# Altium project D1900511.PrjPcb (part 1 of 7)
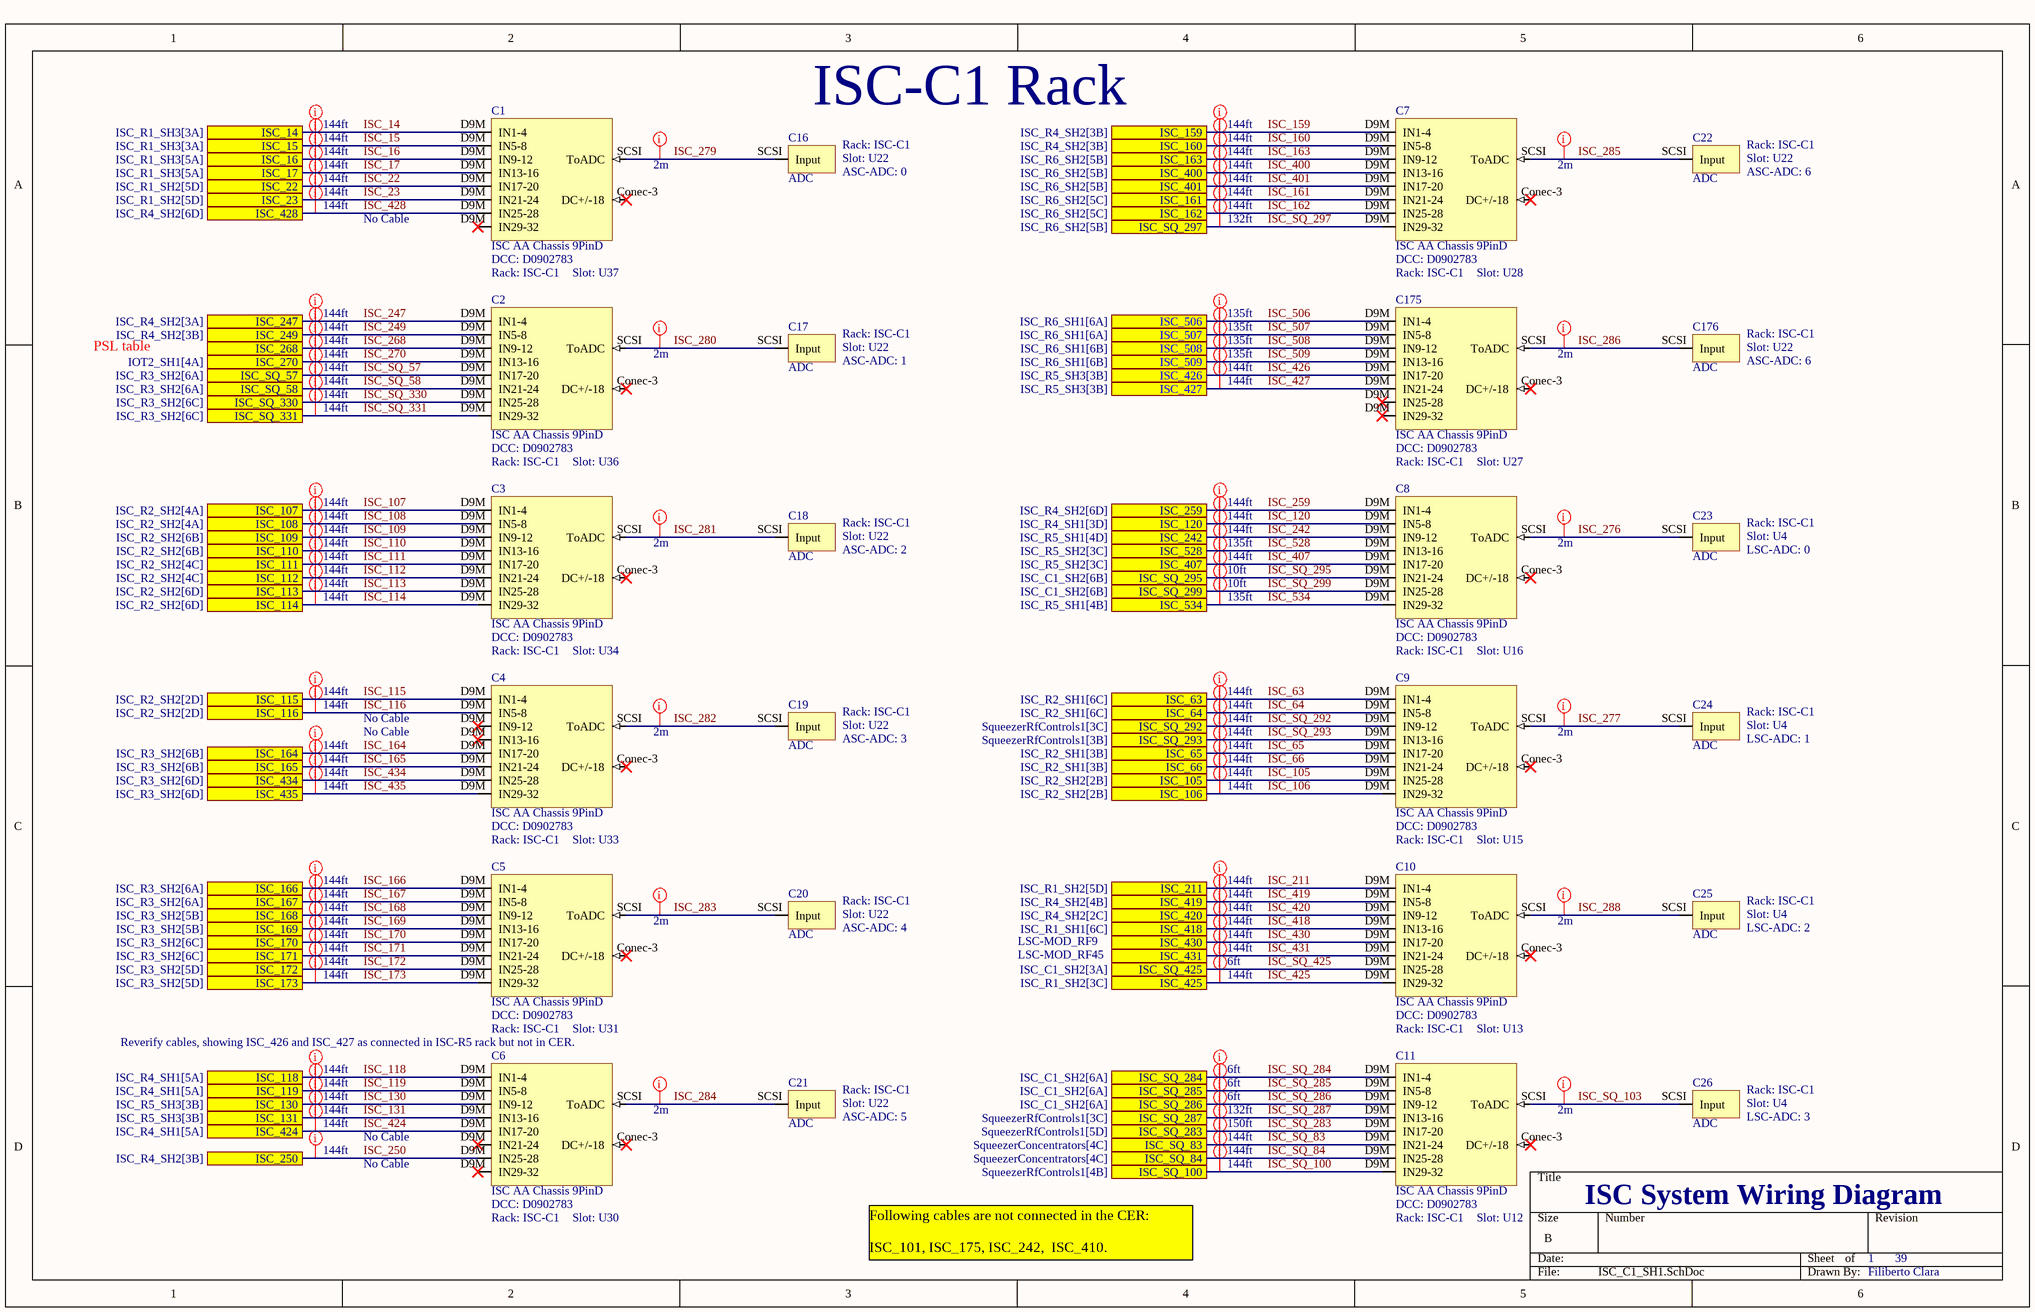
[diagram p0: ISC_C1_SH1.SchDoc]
DCCVER: V11; DCC: D1900511
39 sheets, 544 parts. Net scope: flat (ports and power ports of the same name join across sheets).
Sheets:
  ISC_C1_SH1.SchDoc
  ISC_C1_SH2.SchDoc
  ISC_C2_SH1.SchDoc
  ISC_C2_SH2.SchDoc
  ISC_C3_SH1.SchDoc
  ISC_C3_SH2.SchDoc
  ISC_C3_SH3.SchDoc
  ISC_C4_SH1.SchDoc
  ISC_C4_SH2.SchDoc
  ISC_R1_SH1.SchDoc
  ISC_R1_SH2.SchDoc
  ISC_R1_SH3.SchDoc
  ISC_R2_SH1.SchDoc
  ISC_R2_SH2.SchDoc
  ISC_R4_SH1.SchDoc
  ISC_R4_SH2.SchDoc
  ISC_R3_SH1.SchDoc
  ISC_R3_SH2.SchDoc
  ISC_R5_SH1.SchDoc
  ISC_R5_SH2.SchDoc
  ISC_R5_SH3.SchDoc
  ISC_R6_SH1.SchDoc
  ISC_R6_SH2.SchDoc
  ISCT1_SH1.SchDoc
  ISCT1_SH2.SchDoc
  IOT2_SH1.SchDoc
  IOT2_SH2.SchDoc
  HAM6_SH1.SchDoc
  HAM6_SH2.SchDoc
  SqueezerWfsWiring.SchDoc
  SqueezerInVacControls.SchDoc
  SqueezerFiber.SchDoc
  SqueezerRfDistribution.SchDoc
  SqueezerRfControls1.SchDoc
  SqueezerRfControls2.SchDoc
  SqueezerConcentrators.SchDoc
  SqueezerMiscellaneous.SchDoc
  SqueezerBeckhoff1.SchDoc
  SqueezerBeckhoff2.SchDoc

## Sheet ISC_C1_SH1.SchDoc: ISC System Wiring Diagram
size B; DrawnBy: Filiberto Clara; Engineer: Filiberto Clara; Organization: LIGO Laboratory; Address1: California Institute of Technology; Address2: Massachusetts Institute of Technology; DocumentNumber: D1900511; Revision: V11; SheetNumber: 1; SheetTotal: 39

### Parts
C1  ISC AA Chassis 9PinD  DCC: D0902783  Rack: ISC-C1  Slot: U37
C2  ISC AA Chassis 9PinD  DCC: D0902783  Rack: ISC-C1  Slot: U36
C3  ISC AA Chassis 9PinD  DCC: D0902783  Rack: ISC-C1  Slot: U34
C4  ISC AA Chassis 9PinD  DCC: D0902783  Rack: ISC-C1  Slot: U33
C5  ISC AA Chassis 9PinD  DCC: D0902783  Rack: ISC-C1  Slot: U31
C6  ISC AA Chassis 9PinD  DCC: D0902783  Rack: ISC-C1  Slot: U30
C7  ISC AA Chassis 9PinD  DCC: D0902783  Rack: ISC-C1  Slot: U28
C8  ISC AA Chassis 9PinD  DCC: D0902783  Rack: ISC-C1  Slot: U16
C9  ISC AA Chassis 9PinD  DCC: D0902783  Rack: ISC-C1  Slot: U15
C10  ISC AA Chassis 9PinD  DCC: D0902783  Rack: ISC-C1  Slot: U13
C11  ISC AA Chassis 9PinD  DCC: D0902783  Rack: ISC-C1  Slot: U12
C16  ADC  Rack: ISC-C1  Slot: U22  ASC-ADC: 0
C17  ADC  Rack: ISC-C1  Slot: U22  ASC-ADC: 1
C18  ADC  Rack: ISC-C1  Slot: U22  ASC-ADC: 2
C19  ADC  Rack: ISC-C1  Slot: U22  ASC-ADC: 3
C20  ADC  Rack: ISC-C1  Slot: U22  ASC-ADC: 4
C21  ADC  Rack: ISC-C1  Slot: U22  ASC-ADC: 5
C22  ADC  Rack: ISC-C1  Slot: U22  ASC-ADC: 6
C23  ADC  Rack: ISC-C1  Slot: U4  LSC-ADC: 0
C24  ADC  Rack: ISC-C1  Slot: U4  LSC-ADC: 1
C25  ADC  Rack: ISC-C1  Slot: U4  LSC-ADC: 2
C26  ADC  Rack: ISC-C1  Slot: U4  LSC-ADC: 3
C175  ISC AA Chassis 9PinD  DCC: D0902783  Rack: ISC-C1  Slot: U27
C176  ADC  Rack: ISC-C1  Slot: U22  ASC-ADC: 6

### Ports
ISC_14 (see ISC_R1_SH3[3A]), ISC_15 (see ISC_R1_SH3[3A]), ISC_16 (see ISC_R1_SH3[5A]), ISC_17 (see ISC_R1_SH3[5A]), ISC_22 (see ISC_R1_SH2[5D]), ISC_23 (see ISC_R1_SH2[5D]), ISC_63 (see ISC_R2_SH1[6C]), ISC_64 (see ISC_R2_SH1[6C]), ISC_65 (see ISC_R2_SH1[3B]), ISC_66 (see ISC_R2_SH1[3B]), ISC_105 (see ISC_R2_SH2[2B]), ISC_106 (see ISC_R2_SH2[2B]), ISC_107 (see ISC_R2_SH2[4A]), ISC_108 (see ISC_R2_SH2[4A]), ISC_109 (see ISC_R2_SH2[6B]), ISC_110 (see ISC_R2_SH2[6B]), ISC_111 (see ISC_R2_SH2[4C]), ISC_112 (see ISC_R2_SH2[4C]), ISC_113 (see ISC_R2_SH2[6D]), ISC_114 (see ISC_R2_SH2[6D]), ISC_115 (see ISC_R2_SH2[2D]), ISC_116 (see ISC_R2_SH2[2D]), ISC_118 (see ISC_R4_SH1[5A]), ISC_119 (see ISC_R4_SH1[5A]), ISC_120 (see ISC_R4_SH1[3D]), ISC_130 (see ISC_R5_SH3[3B]), ISC_131 (see ISC_R5_SH3[3B]), ISC_159 (see ISC_R4_SH2[3B]), ISC_160 (see ISC_R4_SH2[3B]), ISC_161 (see ISC_R6_SH2[5C]), ISC_162 (see ISC_R6_SH2[5C]), ISC_163 (see ISC_R6_SH2[5B]), ISC_164 (see ISC_R3_SH2[6B]), ISC_165 (see ISC_R3_SH2[6B]), ISC_166 (see ISC_R3_SH2[6A]), ISC_167 (see ISC_R3_SH2[6A]), ISC_168 (see ISC_R3_SH2[5B]), ISC_169 (see ISC_R3_SH2[5B]), ISC_170 (see ISC_R3_SH2[6C]), ISC_171 (see ISC_R3_SH2[6C]), ISC_172 (see ISC_R3_SH2[5D]), ISC_173 (see ISC_R3_SH2[5D]), ISC_211 (see ISC_R1_SH2[5D]), ISC_242 (see ISC_R5_SH1[4D]), ISC_247 (see ISC_R4_SH2[3A]), ISC_249 (see ISC_R4_SH2[3B]), ISC_250 (see ISC_R4_SH2[3B]), ISC_259 (see ISC_R4_SH2[6D]), ISC_268, ISC_270 (see IOT2_SH1[4A]), ISC_400 (see ISC_R6_SH2[5B]), ISC_401 (see ISC_R6_SH2[5B]), ISC_407 (see ISC_R5_SH2[3C]), ISC_418 (see ISC_R1_SH1[6C]), ISC_419 (see ISC_R4_SH2[4B]), ISC_420 (see ISC_R4_SH2[2C]), ISC_424 (see ISC_R4_SH1[5A]), ISC_425 (see ISC_R1_SH2[3C]), ISC_426 (see ISC_R5_SH3[3B]), ISC_427 (see ISC_R5_SH3[3B]), ISC_428 (see ISC_R4_SH2[6D]), ISC_430, ISC_431, ISC_434 (see ISC_R3_SH2[6D]), ISC_435 (see ISC_R3_SH2[6D]), ISC_506 (see ISC_R6_SH1[6A]), ISC_507 (see ISC_R6_SH1[6A]), ISC_508 (see ISC_R6_SH1[6B]), ISC_509 (see ISC_R6_SH1[6B]), ISC_528 (see ISC_R5_SH2[3C]), ISC_534 (see ISC_R5_SH1[4B]), ISC_SQ_57 (see ISC_R3_SH2[6A]), ISC_SQ_58 (see ISC_R3_SH2[6A]), ISC_SQ_83 (see SqueezerConcentrators[4C]), ISC_SQ_84 (see SqueezerConcentrators[4C]), ISC_SQ_100 (see SqueezerRfControls1[4B]), ISC_SQ_283 (see SqueezerRfControls1[5D]), ISC_SQ_284 (see ISC_C1_SH2[6A]), ISC_SQ_285 (see ISC_C1_SH2[6A]), ISC_SQ_286 (see ISC_C1_SH2[6A]), ISC_SQ_287 (see SqueezerRfControls1[3C]), ISC_SQ_292 (see SqueezerRfControls1[3C]), ISC_SQ_293 (see SqueezerRfControls1[3B]), ISC_SQ_295 (see ISC_C1_SH2[6B]), ISC_SQ_297 (see ISC_R6_SH2[5B]), ISC_SQ_299 (see ISC_C1_SH2[6B]), ISC_SQ_330 (see ISC_R3_SH2[6C]), ISC_SQ_331 (see ISC_R3_SH2[6C]), ISC_SQ_425 (see ISC_C1_SH2[3A])

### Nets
ISC_14: C1.D9M(IN1-4) ; port ISC_14
ISC_15: C1.D9M(IN5-8) ; port ISC_15
ISC_16: C1.D9M(IN9-12) ; port ISC_16
ISC_17: C1.D9M(IN13-16) ; port ISC_17
ISC_22: C1.D9M(IN17-20) ; port ISC_22
ISC_23: C1.D9M(IN21-24) ; port ISC_23
ISC_63: C9.D9M(IN1-4) ; port ISC_63
ISC_64: C9.D9M(IN5-8) ; port ISC_64
ISC_65: C9.D9M(IN17-20) ; port ISC_65
ISC_66: C9.D9M(IN21-24) ; port ISC_66
ISC_105: C9.D9M(IN25-28) ; port ISC_105
ISC_106: C9.D9M(IN29-32) ; port ISC_106
ISC_107: C3.D9M(IN1-4) ; port ISC_107
ISC_108: C3.D9M(IN5-8) ; port ISC_108
ISC_109: C3.D9M(IN9-12) ; port ISC_109
ISC_110: C3.D9M(IN13-16) ; port ISC_110
ISC_111: C3.D9M(IN17-20) ; port ISC_111
ISC_112: C3.D9M(IN21-24) ; port ISC_112
ISC_113: C3.D9M(IN25-28) ; port ISC_113
ISC_114: C3.D9M(IN29-32) ; port ISC_114
ISC_115: C4.D9M(IN1-4) ; port ISC_115
ISC_116: C4.D9M(IN5-8) ; port ISC_116
ISC_118: C6.D9M(IN1-4) ; port ISC_118
ISC_119: C6.D9M(IN5-8) ; port ISC_119
ISC_120: C8.D9M(IN5-8) ; port ISC_120
ISC_130: C6.D9M(IN9-12) ; port ISC_130
ISC_131: C6.D9M(IN13-16) ; port ISC_131
ISC_159: C7.D9M(IN1-4) ; port ISC_159
ISC_160: C7.D9M(IN5-8) ; port ISC_160
ISC_161: C7.D9M(IN21-24) ; port ISC_161
ISC_162: C7.D9M(IN25-28) ; port ISC_162
ISC_163: C7.D9M(IN9-12) ; port ISC_163
ISC_164: C4.D9M(IN17-20) ; port ISC_164
ISC_165: C4.D9M(IN21-24) ; port ISC_165
ISC_166: C5.D9M(IN1-4) ; port ISC_166
ISC_167: C5.D9M(IN5-8) ; port ISC_167
ISC_168: C5.D9M(IN9-12) ; port ISC_168
ISC_169: C5.D9M(IN13-16) ; port ISC_169
ISC_170: C5.D9M(IN17-20) ; port ISC_170
ISC_171: C5.D9M(IN21-24) ; port ISC_171
ISC_172: C5.D9M(IN25-28) ; port ISC_172
ISC_173: C5.D9M(IN29-32) ; port ISC_173
ISC_211: C10.D9M(IN1-4) ; port ISC_211
ISC_242: C8.D9M(IN9-12) ; port ISC_242
ISC_247: C2.D9M(IN1-4) ; port ISC_247
ISC_249: C2.D9M(IN5-8) ; port ISC_249
ISC_250: C6.D9M(IN25-28) ; port ISC_250
ISC_259: C8.D9M(IN1-4) ; port ISC_259
ISC_268: C2.D9M(IN9-12) ; port ISC_268
ISC_270: C2.D9M(IN13-16) ; port ISC_270
ISC_276: C8.SCSI(ToADC) C23.SCSI(Input)
ISC_277: C9.SCSI(ToADC) C24.SCSI(Input)
ISC_279: C1.SCSI(ToADC) C16.SCSI(Input)
ISC_280: C2.SCSI(ToADC) C17.SCSI(Input)
ISC_281: C3.SCSI(ToADC) C18.SCSI(Input)
ISC_282: C4.SCSI(ToADC) C19.SCSI(Input)
ISC_283: C5.SCSI(ToADC) C20.SCSI(Input)
ISC_284: C6.SCSI(ToADC) C21.SCSI(Input)
ISC_285: C7.SCSI(ToADC) C22.SCSI(Input)
ISC_286: C175.SCSI(ToADC) C176.SCSI(Input)
ISC_288: C10.SCSI(ToADC) C25.SCSI(Input)
ISC_400: C7.D9M(IN13-16) ; port ISC_400
ISC_401: C7.D9M(IN17-20) ; port ISC_401
ISC_407: C8.D9M(IN17-20) ; port ISC_407
ISC_418: C10.D9M(IN13-16) ; port ISC_418
ISC_419: C10.D9M(IN5-8) ; port ISC_419
ISC_420: C10.D9M(IN9-12) ; port ISC_420
ISC_424: C6.D9M(IN17-20) ; port ISC_424
ISC_425: C10.D9M(IN29-32) ; port ISC_425
ISC_426: C175.D9M(IN17-20) ; port ISC_426
ISC_427: C175.D9M(IN21-24) ; port ISC_427
ISC_428: C1.D9M(IN25-28) ; port ISC_428
ISC_430: C10.D9M(IN17-20) ; port ISC_430
ISC_431: C10.D9M(IN21-24) ; port ISC_431
ISC_434: C4.D9M(IN25-28) ; port ISC_434
ISC_435: C4.D9M(IN29-32) ; port ISC_435
ISC_506: C175.D9M(IN1-4) ; port ISC_506
ISC_507: C175.D9M(IN5-8) ; port ISC_507
ISC_508: C175.D9M(IN9-12) ; port ISC_508
ISC_509: C175.D9M(IN13-16) ; port ISC_509
ISC_528: C8.D9M(IN13-16) ; port ISC_528
ISC_534: C8.D9M(IN29-32) ; port ISC_534
ISC_SQ_57: C2.D9M(IN17-20) ; port ISC_SQ_57
ISC_SQ_58: C2.D9M(IN21-24) ; port ISC_SQ_58
ISC_SQ_83: C11.D9M(IN21-24) ; port ISC_SQ_83
ISC_SQ_84: C11.D9M(IN25-28) ; port ISC_SQ_84
ISC_SQ_100: C11.D9M(IN29-32) ; port ISC_SQ_100
ISC_SQ_103: C11.SCSI(ToADC) C26.SCSI(Input)
ISC_SQ_283: C11.D9M(IN17-20) ; port ISC_SQ_283
ISC_SQ_284: C11.D9M(IN1-4) ; port ISC_SQ_284
ISC_SQ_285: C11.D9M(IN5-8) ; port ISC_SQ_285
ISC_SQ_286: C11.D9M(IN9-12) ; port ISC_SQ_286
ISC_SQ_287: C11.D9M(IN13-16) ; port ISC_SQ_287
ISC_SQ_292: C9.D9M(IN9-12) ; port ISC_SQ_292
ISC_SQ_293: C9.D9M(IN13-16) ; port ISC_SQ_293
ISC_SQ_295: C8.D9M(IN21-24) ; port ISC_SQ_295
ISC_SQ_297: C7.D9M(IN29-32) ; port ISC_SQ_297
ISC_SQ_299: C8.D9M(IN25-28) ; port ISC_SQ_299
ISC_SQ_330: C2.D9M(IN25-28) ; port ISC_SQ_330
ISC_SQ_331: C2.D9M(IN29-32) ; port ISC_SQ_331
ISC_SQ_425: C10.D9M(IN25-28) ; port ISC_SQ_425

Not connected (* = marked no-connect by the designer): C1 Conec-3(DC+/-18)*; C2 Conec-3(DC+/-18)*; C3 Conec-3(DC+/-18)*; C4 Conec-3(DC+/-18)*; C5 Conec-3(DC+/-18)*; C6 Conec-3(DC+/-18)*; C7 Conec-3(DC+/-18)*; C8 Conec-3(DC+/-18)*; C9 Conec-3(DC+/-18)*; C10 Conec-3(DC+/-18)*; C11 Conec-3(DC+/-18)*; C175 Conec-3(DC+/-18)*

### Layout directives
Length: 2m: ISC_276, ISC_277, ISC_279, ISC_280, ISC_281, ISC_282, ISC_283, ISC_284, ISC_285, ISC_286, ISC_288, ISC_SQ_103
Length: 144ft: ISC_14, ISC_15, ISC_16, ISC_17, ISC_22, ISC_23, ISC_63, ISC_64, ISC_65, ISC_66, ISC_105, ISC_106, ISC_107, ISC_108, ISC_109, ISC_110, ISC_111, ISC_112, ISC_113, ISC_114, ISC_115, ISC_116, ISC_118, ISC_119, ISC_120, ISC_130, ISC_131, ISC_159, ISC_160, ISC_161, ISC_162, ISC_163, ISC_164, ISC_165, ISC_166, ISC_167, ISC_168, ISC_169, ISC_170, ISC_171, ISC_172, ISC_173, ISC_211, ISC_242, ISC_247, ISC_249, ISC_250, ISC_259, ISC_268, ISC_270, ISC_400, ISC_401, ISC_407, ISC_418, ISC_419, ISC_420, ISC_424, ISC_425, ISC_426, ISC_427, ISC_428, ISC_430, ISC_431, ISC_434, ISC_435, ISC_SQ_57, ISC_SQ_58, ISC_SQ_83, ISC_SQ_84, ISC_SQ_100, ISC_SQ_292, ISC_SQ_293, ISC_SQ_330, ISC_SQ_331
Length: 10ft: ISC_SQ_295, ISC_SQ_299
Length: 132ft: ISC_SQ_287, ISC_SQ_297
Length: 6ft: ISC_SQ_284, ISC_SQ_285, ISC_SQ_286, ISC_SQ_425
Length: 150ft: ISC_SQ_283
Length: 135ft: ISC_506, ISC_507, ISC_508, ISC_509, ISC_528, ISC_534

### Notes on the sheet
- (near C16) ISC-C1 Rack
- No Cable
- PSL table
- LSC-MOD_RF9
- LSC-MOD_RF45
- (near C6) Reverify cables, showing ISC_426 and ISC_427 as connected in ISC-R5 rack but not in CER.
- Following cables are not connected in the CER:
  ISC_101, ISC_175, ISC_242,  ISC_410.

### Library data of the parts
C1-C11 C175 = AA_9pinAll: Serial: Sxxxxxxx
C16-C26 C176 = ADC-16: 16 Bit ADC; Serial: Sxxxxxxx; System: ISC; DCC: tbd

## Sheet ISC_C1_SH2.SchDoc: ISC System Wiring Diagram
size B; DrawnBy: Filiberto Clara; Engineer: Filiberto Clara; Organization: LIGO Laboratory; Address1: California Institute of Technology; Address2: Massachusetts Institute of Technology; DocumentNumber: D1900511; Revision: V11; SheetNumber: 2; SheetTotal: 39
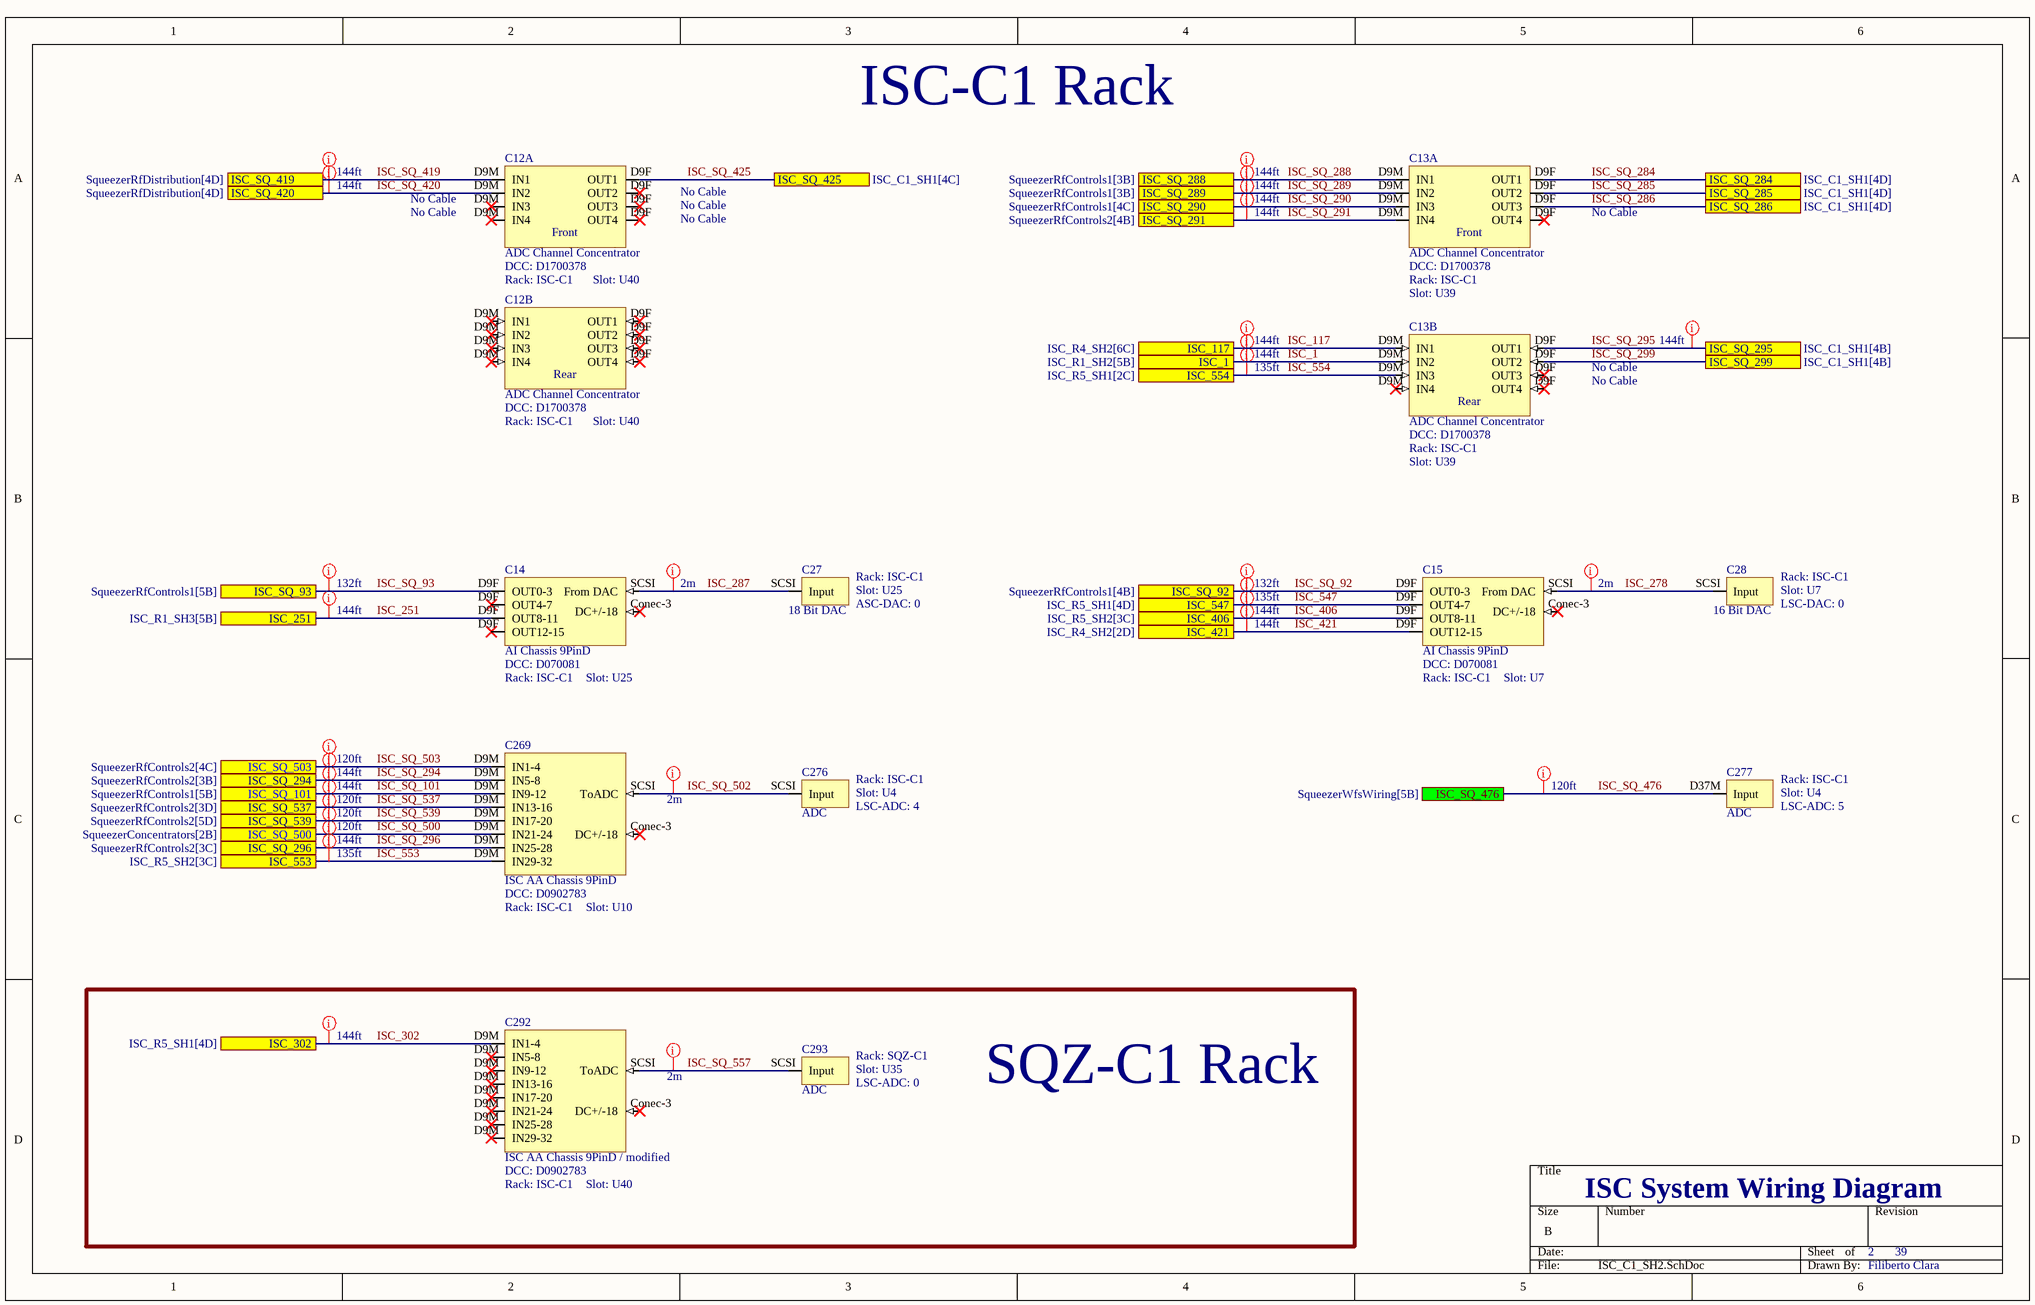
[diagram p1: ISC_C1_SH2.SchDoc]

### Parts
C12  ADC Channel Concentrator  DCC: D1700378  Rack: ISC-C1  Slot: U40  (parts A,B of 2)
C13  ADC Channel Concentrator  DCC: D1700378  Rack: ISC-C1  Slot: U39  (parts A,B of 2)
C14  AI Chassis 9PinD  DCC: D070081  Rack: ISC-C1  Slot: U25
C15  AI Chassis 9PinD  DCC: D070081  Rack: ISC-C1  Slot: U7
C27  18 Bit DAC  Rack: ISC-C1  Slot: U25  ASC-DAC: 0
C28  16 Bit DAC  Rack: ISC-C1  Slot: U7  LSC-DAC: 0
C269  ISC AA Chassis 9PinD  DCC: D0902783  Rack: ISC-C1  Slot: U10
C276  ADC  Rack: ISC-C1  Slot: U4  LSC-ADC: 4
C277  ADC  Rack: ISC-C1  Slot: U4  LSC-ADC: 5
C292  ISC AA Chassis 9PinD / modified  DCC: D0902783  Rack: ISC-C1  Slot: U40
C293  ADC  Rack: SQZ-C1  Slot: U35  LSC-ADC: 0

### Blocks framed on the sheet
SQZ-C1 Rack: C292 C293

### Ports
ISC_1 (see ISC_R1_SH2[5B]), ISC_117 (see ISC_R4_SH2[6C]), ISC_251 (see ISC_R1_SH3[5B]), ISC_302 (see ISC_R5_SH1[4D]), ISC_406 (see ISC_R5_SH2[3C]), ISC_421 (see ISC_R4_SH2[2D]), ISC_547 (see ISC_R5_SH1[4D]), ISC_553 (see ISC_R5_SH2[3C]), ISC_554 (see ISC_R5_SH1[2C]), ISC_SQ_92 (see SqueezerRfControls1[4B]), ISC_SQ_93 (see SqueezerRfControls1[5B]), ISC_SQ_101 (see SqueezerRfControls1[5B]), ISC_SQ_284 (see ISC_C1_SH1[4D]), ISC_SQ_285 (see ISC_C1_SH1[4D]), ISC_SQ_286 (see ISC_C1_SH1[4D]), ISC_SQ_288 (see SqueezerRfControls1[3B]), ISC_SQ_289 (see SqueezerRfControls1[3B]), ISC_SQ_290 (see SqueezerRfControls1[4C]), ISC_SQ_291 (see SqueezerRfControls2[4B]), ISC_SQ_294 (see SqueezerRfControls2[3B]), ISC_SQ_295 (see ISC_C1_SH1[4B]), ISC_SQ_296 (see SqueezerRfControls2[3C]), ISC_SQ_299 (see ISC_C1_SH1[4B]), ISC_SQ_419 (see SqueezerRfDistribution[4D]), ISC_SQ_420 (see SqueezerRfDistribution[4D]), ISC_SQ_425 (see ISC_C1_SH1[4C]), ISC_SQ_476 (see SqueezerWfsWiring[5B]), ISC_SQ_500 (see SqueezerConcentrators[2B]), ISC_SQ_503 (see SqueezerRfControls2[4C]), ISC_SQ_537 (see SqueezerRfControls2[3D]), ISC_SQ_539 (see SqueezerRfControls2[5D])

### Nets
ISC_1: C13.D9M(IN2) ; port ISC_1
ISC_117: C13.D9M(IN1) ; port ISC_117
ISC_251: C14.D9F(OUT8-11) ; port ISC_251
ISC_278: C15.SCSI(From_DAC) C28.SCSI(Input)
ISC_287: C14.SCSI(From_DAC) C27.SCSI(Input)
ISC_302: C292.D9M(IN1-4) ; port ISC_302
ISC_406: C15.D9F(OUT8-11) ; port ISC_406
ISC_421: C15.D9F(OUT12-15) ; port ISC_421
ISC_547: C15.D9F(OUT4-7) ; port ISC_547
ISC_553: C269.D9M(IN29-32) ; port ISC_553
ISC_554: C13.D9M(IN3) ; port ISC_554
ISC_SQ_92: C15.D9F(OUT0-3) ; port ISC_SQ_92
ISC_SQ_93: C14.D9F(OUT0-3) ; port ISC_SQ_93
ISC_SQ_101: C269.D9M(IN9-12) ; port ISC_SQ_101
ISC_SQ_284: C13.D9F(OUT1) ; port ISC_SQ_284
ISC_SQ_285: C13.D9F(OUT2) ; port ISC_SQ_285
ISC_SQ_286: C13.D9F(OUT3) ; port ISC_SQ_286
ISC_SQ_288: C13.D9M(IN1) ; port ISC_SQ_288
ISC_SQ_289: C13.D9M(IN2) ; port ISC_SQ_289
ISC_SQ_290: C13.D9M(IN3) ; port ISC_SQ_290
ISC_SQ_291: C13.D9M(IN4) ; port ISC_SQ_291
ISC_SQ_294: C269.D9M(IN5-8) ; port ISC_SQ_294
ISC_SQ_295: C13.D9F(OUT1) ; port ISC_SQ_295
ISC_SQ_296: C269.D9M(IN25-28) ; port ISC_SQ_296
ISC_SQ_299: C13.D9F(OUT2) ; port ISC_SQ_299
ISC_SQ_419: C12.D9M(IN1) ; port ISC_SQ_419
ISC_SQ_420: C12.D9M(IN2) ; port ISC_SQ_420
ISC_SQ_425: C12.D9F(OUT1) ; port ISC_SQ_425
ISC_SQ_476: C277.D37M(Input) ; port ISC_SQ_476
ISC_SQ_500: C269.D9M(IN21-24) ; port ISC_SQ_500
ISC_SQ_502: C269.SCSI(ToADC) C276.SCSI(Input)
ISC_SQ_503: C269.D9M(IN1-4) ; port ISC_SQ_503
ISC_SQ_537: C269.D9M(IN13-16) ; port ISC_SQ_537
ISC_SQ_539: C269.D9M(IN17-20) ; port ISC_SQ_539
ISC_SQ_557: C292.SCSI(ToADC) C293.SCSI(Input)

Not connected (* = marked no-connect by the designer): C14 Conec-3(DC+/-18)*; C15 Conec-3(DC+/-18)*; C269 Conec-3(DC+/-18)*; C292 Conec-3(DC+/-18)*

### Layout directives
Length: 144ft: ISC_1, ISC_117, ISC_251, ISC_302, ISC_406, ISC_421, ISC_SQ_101, ISC_SQ_288, ISC_SQ_289, ISC_SQ_290, ISC_SQ_291, ISC_SQ_294, ISC_SQ_295, ISC_SQ_296, ISC_SQ_419, ISC_SQ_420
Length: 2m: ISC_278, ISC_287, ISC_SQ_502, ISC_SQ_557
Length: 132ft: ISC_SQ_92, ISC_SQ_93
Length: 120ft: ISC_SQ_476, ISC_SQ_500, ISC_SQ_503, ISC_SQ_537, ISC_SQ_539
Length: 135ft: ISC_547, ISC_553, ISC_554

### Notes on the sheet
- ISC-C1 Rack
- (near C12) No Cable
- No Cable

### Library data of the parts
C12 C13 = ADC Channel Concentrator: Serial: Sxxxxxxx; System: ISC
C14 C15 = AI_9pinAll: Serial: Sxxxxxxx; System: ISC
C27 = DAC_18: Serial: Sxxxxxxx; System: ISC; DCC: tbd
C28 = DAC_18: 18 Bit DAC; Serial: Sxxxxxxx; System: ISC; DCC: tbd
C269 = AA_9pinAll: Serial: Sxxxxxxx
C276 C277 C293 = ADC-16: as C16 on sheet ISC_C1_SH1
C292 = AA_9pinAll: ISC AA Chassis 9PinD; Serial: Sxxxxxxx

## Sheet ISC_C2_SH1.SchDoc: ISC System Wiring Diagram
size B; DrawnBy: Filiberto Clara; Engineer: Filiberto Clara; Organization: LIGO Laboratory; Address1: California Institute of Technology; Address2: Massachusetts Institute of Technology; DocumentNumber: D1900511; Revision: V11; SheetNumber: 3; SheetTotal: 39
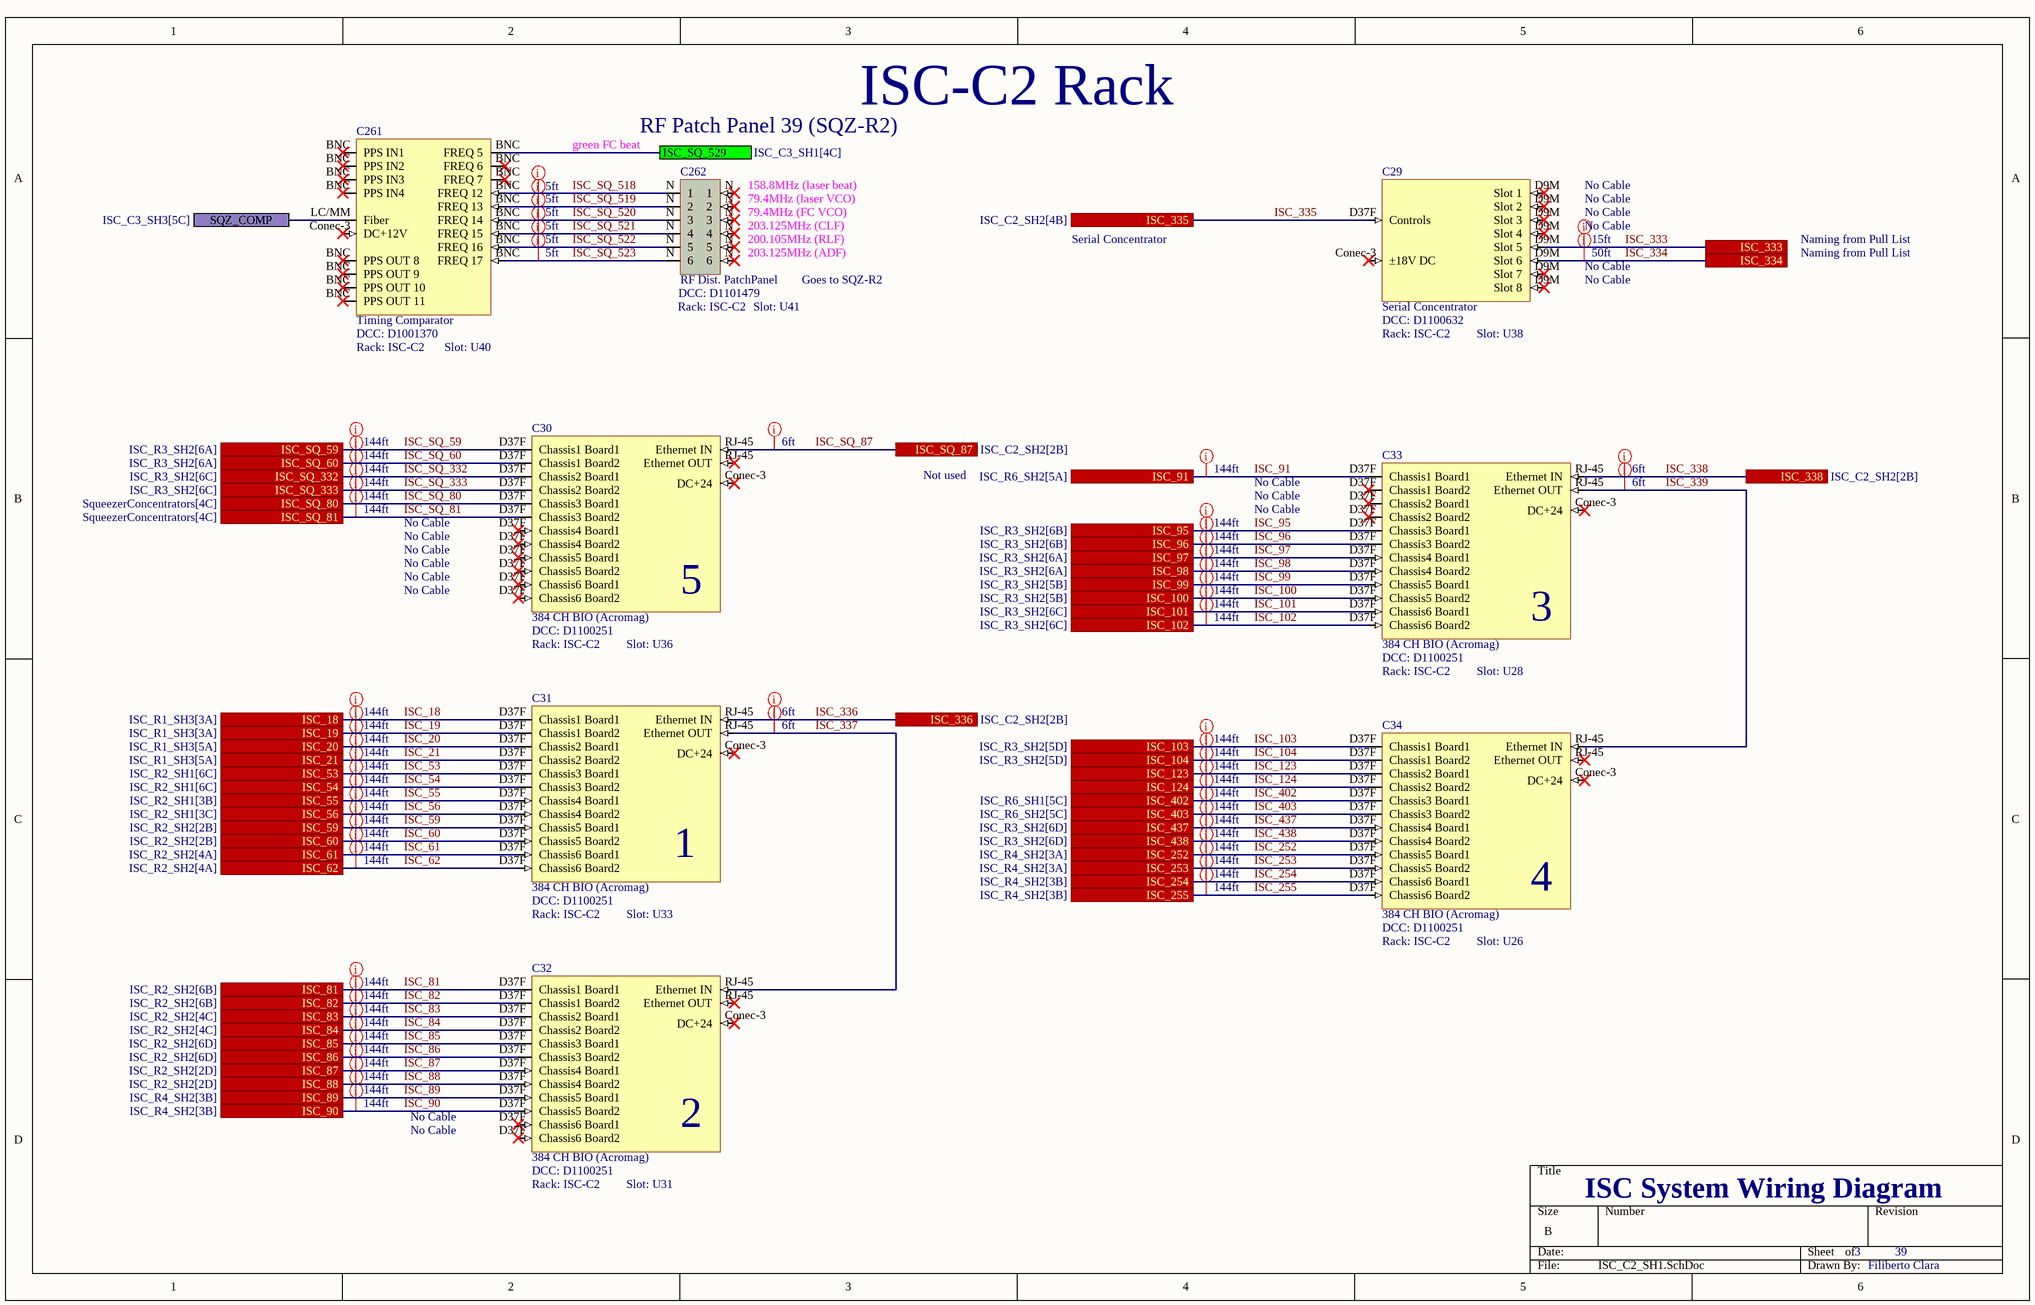
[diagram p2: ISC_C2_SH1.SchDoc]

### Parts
C29  Serial Concentrator  DCC: D1100632  Rack: ISC-C2  Slot: U38
C30  384 CH BIO (Acromag)  DCC: D1100251  Rack: ISC-C2  Slot: U36
C31  384 CH BIO (Acromag)  DCC: D1100251  Rack: ISC-C2  Slot: U33
C32  384 CH BIO (Acromag)  DCC: D1100251  Rack: ISC-C2  Slot: U31
C33  384 CH BIO (Acromag)  DCC: D1100251  Rack: ISC-C2  Slot: U28
C34  384 CH BIO (Acromag)  DCC: D1100251  Rack: ISC-C2  Slot: U26
C261  Timing Comparator  DCC: D1001370  Rack: ISC-C2  Slot: U40
C262  RF Dist. PatchPanel  DCC: D1101479  Rack: ISC-C2  Slot: U41

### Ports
ISC_18 (see ISC_R1_SH3[3A]), ISC_19 (see ISC_R1_SH3[3A]), ISC_20 (see ISC_R1_SH3[5A]), ISC_21 (see ISC_R1_SH3[5A]), ISC_53 (see ISC_R2_SH1[6C]), ISC_54 (see ISC_R2_SH1[6C]), ISC_55 (see ISC_R2_SH1[3B]), ISC_56 (see ISC_R2_SH1[3C]), ISC_59 (see ISC_R2_SH2[2B]), ISC_60 (see ISC_R2_SH2[2B]), ISC_61 (see ISC_R2_SH2[4A]), ISC_62 (see ISC_R2_SH2[4A]), ISC_81 (see ISC_R2_SH2[6B]), ISC_82 (see ISC_R2_SH2[6B]), ISC_83 (see ISC_R2_SH2[4C]), ISC_84 (see ISC_R2_SH2[4C]), ISC_85 (see ISC_R2_SH2[6D]), ISC_86 (see ISC_R2_SH2[6D]), ISC_87 (see ISC_R2_SH2[2D]), ISC_88 (see ISC_R2_SH2[2D]), ISC_89 (see ISC_R4_SH2[3B]), ISC_90 (see ISC_R4_SH2[3B]), ISC_91 (see ISC_R6_SH2[5A]), ISC_95 (see ISC_R3_SH2[6B]), ISC_96 (see ISC_R3_SH2[6B]), ISC_97 (see ISC_R3_SH2[6A]), ISC_98 (see ISC_R3_SH2[6A]), ISC_99 (see ISC_R3_SH2[5B]), ISC_100 (see ISC_R3_SH2[5B]), ISC_101 (see ISC_R3_SH2[6C]), ISC_102 (see ISC_R3_SH2[6C]), ISC_103 (see ISC_R3_SH2[5D]), ISC_104 (see ISC_R3_SH2[5D]), ISC_123, ISC_124, ISC_252 (see ISC_R4_SH2[3A]), ISC_253 (see ISC_R4_SH2[3A]), ISC_254 (see ISC_R4_SH2[3B]), ISC_255 (see ISC_R4_SH2[3B]), ISC_333, ISC_334, ISC_335 (see ISC_C2_SH2[4B]), ISC_336 (see ISC_C2_SH2[2B]), ISC_338 (see ISC_C2_SH2[2B]), ISC_402 (see ISC_R6_SH1[5C]), ISC_403 (see ISC_R6_SH2[5C]), ISC_437 (see ISC_R3_SH2[6D]), ISC_438 (see ISC_R3_SH2[6D]), ISC_SQ_59 (see ISC_R3_SH2[6A]), ISC_SQ_60 (see ISC_R3_SH2[6A]), ISC_SQ_80 (see SqueezerConcentrators[4C]), ISC_SQ_81 (see SqueezerConcentrators[4C]), ISC_SQ_87 (see ISC_C2_SH2[2B]), ISC_SQ_332 (see ISC_R3_SH2[6C]), ISC_SQ_333 (see ISC_R3_SH2[6C]), ISC_SQ_529 (see ISC_C3_SH1[4C]), SQZ_COMP (see ISC_C3_SH3[5C])

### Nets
ISC_18: C31.D37F(Chassis1_Board1) ; port ISC_18
ISC_19: C31.D37F(Chassis1_Board2) ; port ISC_19
ISC_20: C31.D37F(Chassis2_Board1) ; port ISC_20
ISC_21: C31.D37F(Chassis2_Board2) ; port ISC_21
ISC_53: C31.D37F(Chassis3_Board1) ; port ISC_53
ISC_54: C31.D37F(Chassis3_Board2) ; port ISC_54
ISC_55: C31.D37F(Chassis4_Board1) ; port ISC_55
ISC_56: C31.D37F(Chassis4_Board2) ; port ISC_56
ISC_59: C31.D37F(Chassis5_Board1) ; port ISC_59
ISC_60: C31.D37F(Chassis5_Board2) ; port ISC_60
ISC_61: C31.D37F(Chassis6_Board1) ; port ISC_61
ISC_62: C31.D37F(Chassis6_Board2) ; port ISC_62
ISC_81: C32.D37F(Chassis1_Board1) ; port ISC_81
ISC_82: C32.D37F(Chassis1_Board2) ; port ISC_82
ISC_83: C32.D37F(Chassis2_Board1) ; port ISC_83
ISC_84: C32.D37F(Chassis2_Board2) ; port ISC_84
ISC_85: C32.D37F(Chassis3_Board1) ; port ISC_85
ISC_86: C32.D37F(Chassis3_Board2) ; port ISC_86
ISC_87: C32.D37F(Chassis4_Board1) ; port ISC_87
ISC_88: C32.D37F(Chassis4_Board2) ; port ISC_88
ISC_89: C32.D37F(Chassis5_Board1) ; port ISC_89
ISC_90: C32.D37F(Chassis5_Board2) ; port ISC_90
ISC_91: C33.D37F(Chassis1_Board1) ; port ISC_91
ISC_95: C33.D37F(Chassis3_Board1) ; port ISC_95
ISC_96: C33.D37F(Chassis3_Board2) ; port ISC_96
ISC_97: C33.D37F(Chassis4_Board1) ; port ISC_97
ISC_98: C33.D37F(Chassis4_Board2) ; port ISC_98
ISC_99: C33.D37F(Chassis5_Board1) ; port ISC_99
ISC_100: C33.D37F(Chassis5_Board2) ; port ISC_100
ISC_101: C33.D37F(Chassis6_Board1) ; port ISC_101
ISC_102: C33.D37F(Chassis6_Board2) ; port ISC_102
ISC_103: C34.D37F(Chassis1_Board1) ; port ISC_103
ISC_104: C34.D37F(Chassis1_Board2) ; port ISC_104
ISC_123: C34.D37F(Chassis2_Board1) ; port ISC_123
ISC_124: C34.D37F(Chassis2_Board2) ; port ISC_124
ISC_252: C34.D37F(Chassis5_Board1) ; port ISC_252
ISC_253: C34.D37F(Chassis5_Board2) ; port ISC_253
ISC_254: C34.D37F(Chassis6_Board1) ; port ISC_254
ISC_255: C34.D37F(Chassis6_Board2) ; port ISC_255
ISC_333: C29.D9M(Slot_1) ; port ISC_333
ISC_334: C29.D9M(Slot_6) ; port ISC_334
ISC_335: C29.D37F(Controls) ; port ISC_335
ISC_336: C31.RJ-45(Ethernet_IN) ; port ISC_336
ISC_337: C31.RJ-45(Ethernet_OUT) C32.RJ-45(Ethernet_IN)
ISC_338: C33.RJ-45(Ethernet_IN) ; port ISC_338
ISC_339: C33.RJ-45(Ethernet_OUT) C34.RJ-45(Ethernet_IN)
ISC_402: C34.D37F(Chassis3_Board1) ; port ISC_402
ISC_403: C34.D37F(Chassis3_Board2) ; port ISC_403
ISC_437: C34.D37F(Chassis4_Board1) ; port ISC_437
ISC_438: C34.D37F(Chassis4_Board2) ; port ISC_438
ISC_SQ_59: C30.D37F(Chassis1_Board1) ; port ISC_SQ_59
ISC_SQ_60: C30.D37F(Chassis1_Board2) ; port ISC_SQ_60
ISC_SQ_80: C30.D37F(Chassis3_Board1) ; port ISC_SQ_80
ISC_SQ_81: C30.D37F(Chassis3_Board2) ; port ISC_SQ_81
ISC_SQ_87: C30.RJ-45(Ethernet_IN) ; port ISC_SQ_87
ISC_SQ_332: C30.D37F(Chassis2_Board1) ; port ISC_SQ_332
ISC_SQ_333: C30.D37F(Chassis2_Board2) ; port ISC_SQ_333
ISC_SQ_518: C261.BNC(FREQ_12) C262.N(1)
ISC_SQ_519: C261.BNC(FREQ_13) C262.N(2)
ISC_SQ_520: C261.BNC(FREQ_14) C262.N(3)
ISC_SQ_521: C261.BNC(FREQ_15) C262.N(4)
ISC_SQ_522: C261.BNC(FREQ_16) C262.N(5)
ISC_SQ_523: C261.BNC(FREQ_17) C262.N(6)
ISC_SQ_529: C261.BNC(PPS_IN1) ; port ISC_SQ_529
SQZ_COMP: C261.LC/MM(Fiber) ; port SQZ_COMP

Not connected (* = marked no-connect by the designer): C29 Conec-3(±18V_DC)*; C30 Conec-3(DC+24)*; C31 Conec-3(DC+24)*; C32 Conec-3(DC+24)*; C33 Conec-3(DC+24)*; C34 Conec-3(DC+24)*; C261 Conec-3(DC+12V)*

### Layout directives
Length: 144ft: ISC_18, ISC_19, ISC_20, ISC_21, ISC_53, ISC_54, ISC_55, ISC_56, ISC_59, ISC_60, ISC_61, ISC_62, ISC_81, ISC_82, ISC_83, ISC_84, ISC_85, ISC_86, ISC_87, ISC_88, ISC_89, ISC_90, ISC_91, ISC_95, ISC_96, ISC_97, ISC_98, ISC_99, ISC_100, ISC_101, ISC_102, ISC_103, ISC_104, ISC_123, ISC_124, ISC_252, ISC_253, ISC_254, ISC_255, ISC_402, ISC_403, ISC_437, ISC_438, ISC_SQ_59, ISC_SQ_60, ISC_SQ_80, ISC_SQ_81, ISC_SQ_332, ISC_SQ_333
Length: 6ft: ISC_336, ISC_337, ISC_338, ISC_339, ISC_SQ_87
Length: 15ft: ISC_333
Length: 50ft: ISC_334
Length: 5ft: ISC_SQ_518, ISC_SQ_519, ISC_SQ_520, ISC_SQ_521, ISC_SQ_522, ISC_SQ_523

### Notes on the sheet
- ISC-C2 Rack
- (near C262) green FC beat
- RF Patch Panel 39 (SQZ-R2)
- (near C262) 158.8MHz (laser beat)
- (near C262) 79.4MHz (laser VCO)
- (near C262) 203.125MHz (CLF)
- (near C262) 79.4MHz (FC VCO)
- (near C262) 200.105MHz (RLF)
- Serial Concentrator
- No Cable
- Naming from Pull List
- (near C262) 203.125MHz (ADF)
- Goes to SQZ-R2
- Not used
- (near C30) 5
- (near C33) 3
- (near C31) 1
- (near C34) 4
- (near C32) 2

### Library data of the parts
C29 = Serial Concentrator: Serial: Sxxxxxxx; System: ISC
C30-C34 = 384 CH BIO (Acromag): Serial: Sxxxxxxx; System: ISC
C261 = Timing Comparator: Serial: Sxxxxxxx; System: ISC
C262 = RF Dist. PatchPanel: Serial: Sxxxxxxx; System: ISC

## Sheet ISC_C2_SH2.SchDoc: ISC System Wiring Diagram
size C; DrawnBy: Filiberto Clara; Engineer: Filiberto Clara; Organization: LIGO Laboratory; Address1: California Institute of Technology; Address2: Massachusetts Institute of Technology; DocumentNumber: D1900511; Revision: V11; SheetNumber: 4; SheetTotal: 39
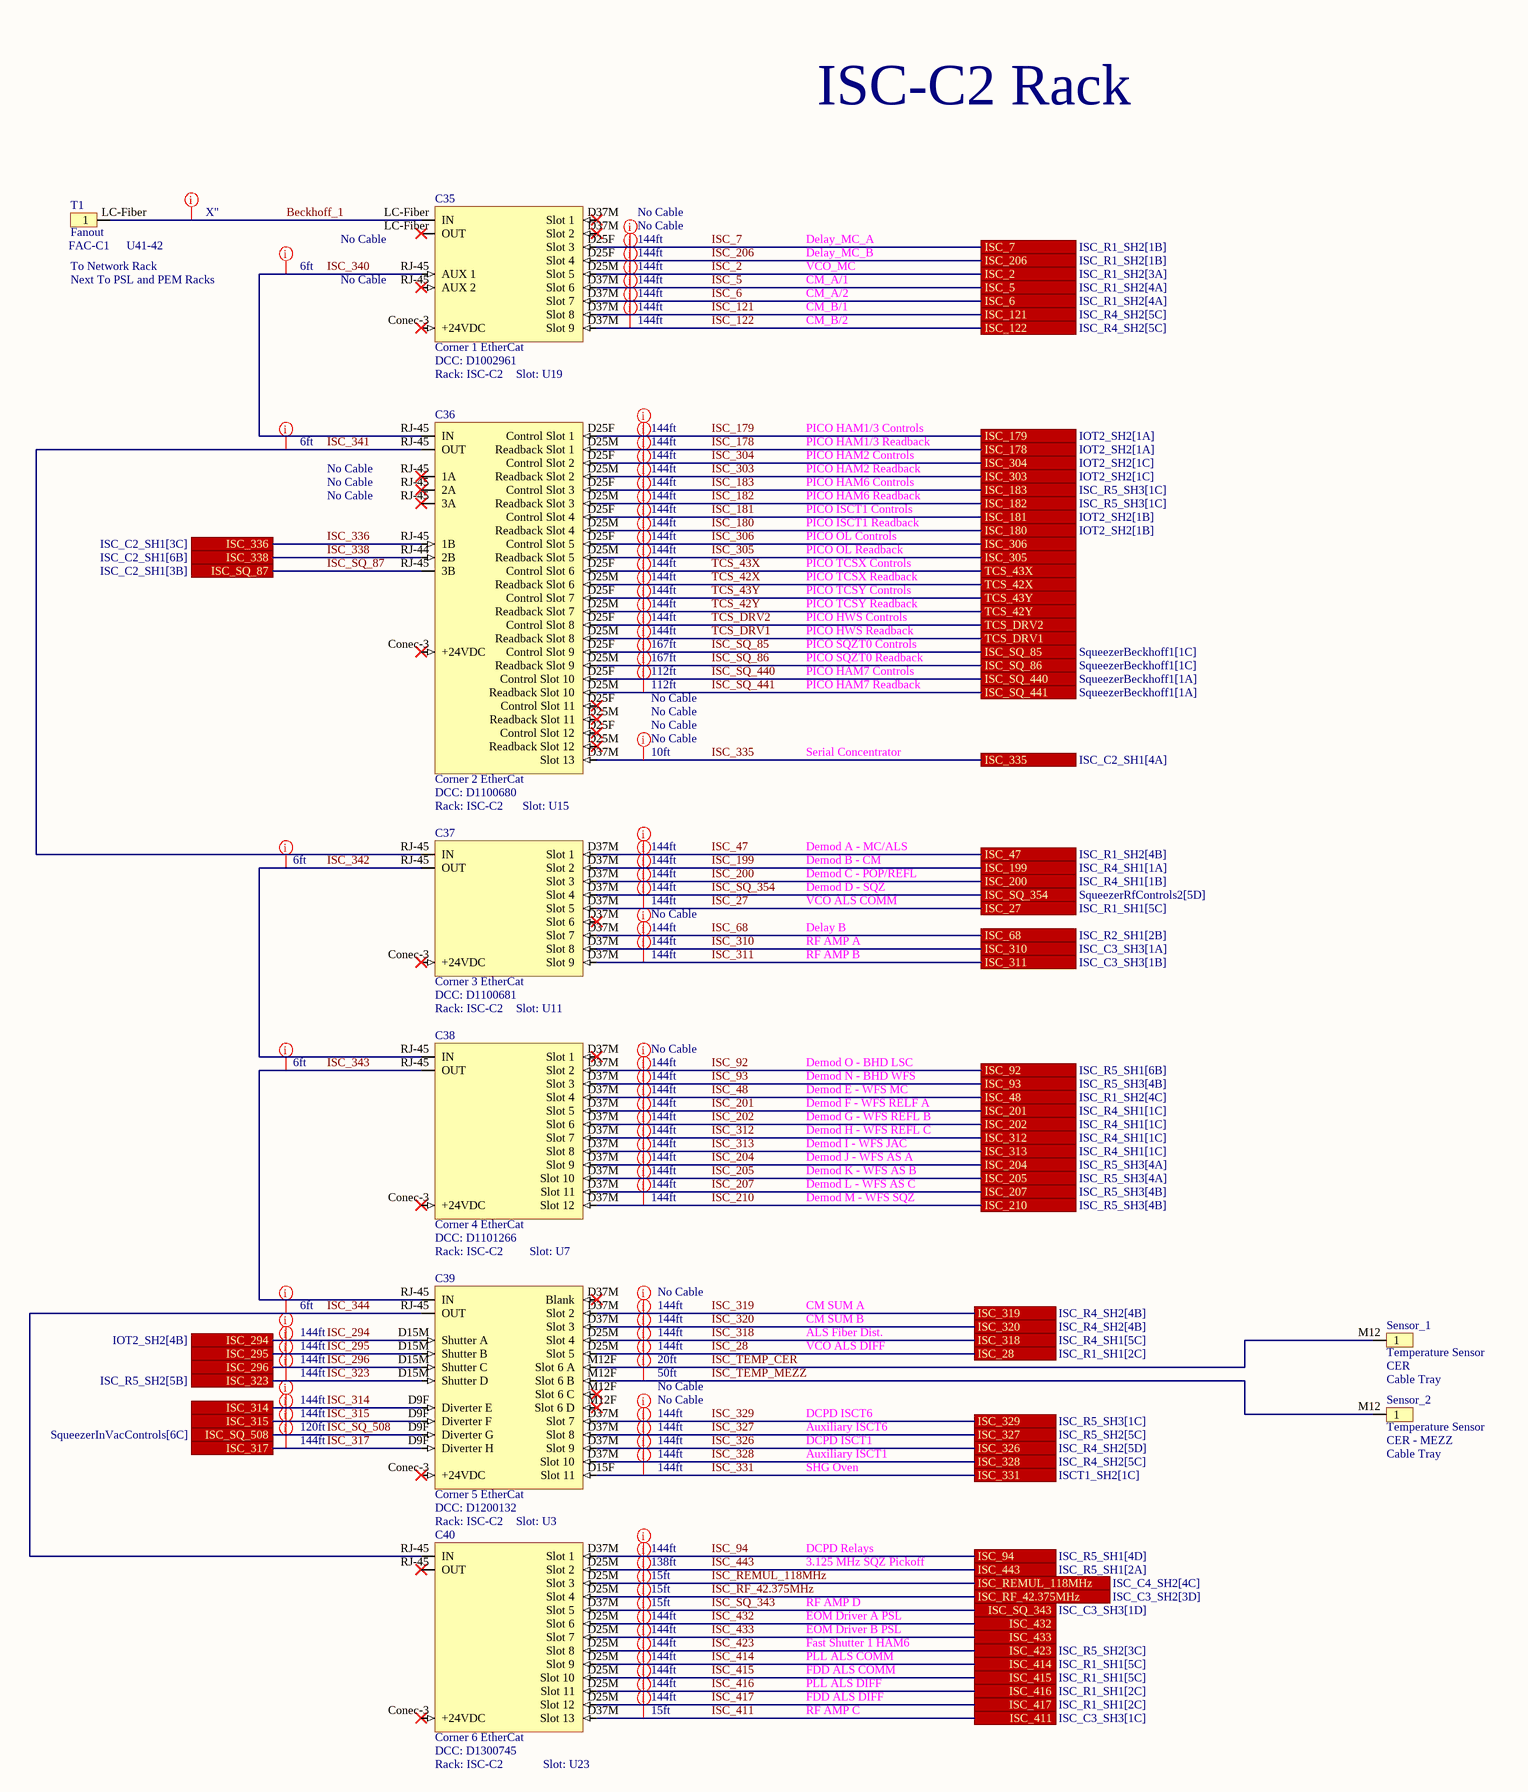
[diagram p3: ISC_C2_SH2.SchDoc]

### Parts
C35  Corner 1 EtherCat  DCC: D1002961  Rack: ISC-C2  Slot: U19
C36  Corner 2 EtherCat  DCC: D1100680  Rack: ISC-C2  Slot: U15
C37  Corner 3 EtherCat  DCC: D1100681  Rack: ISC-C2  Slot: U11
C38  Corner 4 EtherCat  DCC: D1101266  Rack: ISC-C2  Slot: U7
C39  Corner 5 EtherCat  DCC: D1200132  Rack: ISC-C2  Slot: U3
C40  Corner 6 EtherCat  DCC: D1300745  Rack: ISC-C2  Slot: U23
Sensor_1  Temperature Sensor  Rack: CER  Slot: Cable Tray
Sensor_2  Temperature Sensor  Rack: CER - MEZZ  Slot: Cable Tray
T1  Fanout  Rack: FAC-C1  Slot: U41-42

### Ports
ISC_2 (see ISC_R1_SH2[3A]), ISC_5 (see ISC_R1_SH2[4A]), ISC_6 (see ISC_R1_SH2[4A]), ISC_7 (see ISC_R1_SH2[1B]), ISC_27 (see ISC_R1_SH1[5C]), ISC_28 (see ISC_R1_SH1[2C]), ISC_47 (see ISC_R1_SH2[4B]), ISC_48 (see ISC_R1_SH2[4C]), ISC_68 (see ISC_R2_SH1[2B]), ISC_92 (see ISC_R5_SH1[6B]), ISC_93 (see ISC_R5_SH3[4B]), ISC_94 (see ISC_R5_SH1[4D]), ISC_121 (see ISC_R4_SH2[5C]), ISC_122 (see ISC_R4_SH2[5C]), ISC_178 (see IOT2_SH2[1A]), ISC_179 (see IOT2_SH2[1A]), ISC_180 (see IOT2_SH2[1B]), ISC_181 (see IOT2_SH2[1B]), ISC_182 (see ISC_R5_SH3[1C]), ISC_183 (see ISC_R5_SH3[1C]), ISC_199 (see ISC_R4_SH1[1A]), ISC_200 (see ISC_R4_SH1[1B]), ISC_201 (see ISC_R4_SH1[1C]), ISC_202 (see ISC_R4_SH1[1C]), ISC_204 (see ISC_R5_SH3[4A]), ISC_205 (see ISC_R5_SH3[4A]), ISC_206 (see ISC_R1_SH2[1B]), ISC_207 (see ISC_R5_SH3[4B]), ISC_210 (see ISC_R5_SH3[4B]), ISC_294 (see IOT2_SH2[4B]), ISC_295, ISC_296, ISC_303 (see IOT2_SH2[1C]), ISC_304 (see IOT2_SH2[1C]), ISC_305, ISC_306, ISC_310 (see ISC_C3_SH3[1A]), ISC_311 (see ISC_C3_SH3[1B]), ISC_312 (see ISC_R4_SH1[1C]), ISC_313 (see ISC_R4_SH1[1C]), ISC_314, ISC_315, ISC_317, ISC_318 (see ISC_R4_SH1[5C]), ISC_319 (see ISC_R4_SH2[4B]), ISC_320 (see ISC_R4_SH2[4B]), ISC_323 (see ISC_R5_SH2[5B]), ISC_326 (see ISC_R4_SH2[5D]), ISC_327 (see ISC_R5_SH2[5C]), ISC_328 (see ISC_R4_SH2[5C]), ISC_329 (see ISC_R5_SH3[1C]), ISC_331 (see ISCT1_SH2[1C]), ISC_335 (see ISC_C2_SH1[4A]), ISC_336 (see ISC_C2_SH1[3C]), ISC_338 (see ISC_C2_SH1[6B]), ISC_411 (see ISC_C3_SH3[1C]), ISC_414 (see ISC_R1_SH1[5C]), ISC_415 (see ISC_R1_SH1[5C]), ISC_416 (see ISC_R1_SH1[2C]), ISC_417 (see ISC_R1_SH1[2C]), ISC_423 (see ISC_R5_SH2[3C]), ISC_432, ISC_433, ISC_443 (see ISC_R5_SH1[2A]), ISC_REMUL_118MHz (see ISC_C4_SH2[4C]), ISC_RF_42.375MHz (see ISC_C3_SH2[3D]), ISC_SQ_85 (see SqueezerBeckhoff1[1C]), ISC_SQ_86 (see SqueezerBeckhoff1[1C]), ISC_SQ_87 (see ISC_C2_SH1[3B]), ISC_SQ_343 (see ISC_C3_SH3[1D]), ISC_SQ_354 (see SqueezerRfControls2[5D]), ISC_SQ_440 (see SqueezerBeckhoff1[1A]), ISC_SQ_441 (see SqueezerBeckhoff1[1A]), ISC_SQ_508 (see SqueezerInVacControls[6C]), TCS_42X, TCS_42Y, TCS_43X, TCS_43Y, TCS_DRV1, TCS_DRV2

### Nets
Beckhoff_1: C35.LC-Fiber(IN) T1.LC-Fiber(1)
ISC_2: C35.D25M(Slot_5) ; port ISC_2
ISC_5: C35.D37M(Slot_1) ; port ISC_5
ISC_6: C35.D37M(Slot_7) ; port ISC_6
ISC_7: C35.D25F(Slot_3) ; port ISC_7
ISC_27: C37.D37M(Slot_5) ; port ISC_27
ISC_28: C39.D25M(Slot_5) ; port ISC_28
ISC_47: C37.D37M(Slot_1) ; port ISC_47
ISC_48: C38.D37M(Slot_4) ; port ISC_48
ISC_68: C37.D37M(Slot_7) ; port ISC_68
ISC_92: C38.D37M(Slot_1) ; port ISC_92
ISC_93: C38.D37M(Slot_3) ; port ISC_93
ISC_94: C40.D37M(Slot_1) ; port ISC_94
ISC_121: C35.D37M(Slot_8) ; port ISC_121
ISC_122: C35.D37M(Slot_9) ; port ISC_122
ISC_178: C36.D25M(Readback_Slot_1) ; port ISC_178
ISC_179: C36.D25F(Control_Slot_1) ; port ISC_179
ISC_180: C36.D25M(Readback_Slot_4) ; port ISC_180
ISC_181: C36.D25F(Control_Slot_4) ; port ISC_181
ISC_182: C36.D25M(Readback_Slot_3) ; port ISC_182
ISC_183: C36.D25F(Control_Slot_3) ; port ISC_183
ISC_199: C37.D37M(Slot_2) ; port ISC_199
ISC_200: C37.D37M(Slot_3) ; port ISC_200
ISC_201: C38.D37M(Slot_5) ; port ISC_201
ISC_202: C38.D37M(Slot_6) ; port ISC_202
ISC_204: C38.D37M(Slot_9) ; port ISC_204
ISC_205: C38.D37M(Slot_10) ; port ISC_205
ISC_206: C35.D25F(Slot_4) ; port ISC_206
ISC_207: C38.D37M(Slot_11) ; port ISC_207
ISC_210: C38.D37M(Slot_12) ; port ISC_210
ISC_294: C39.D15M(Shutter_A) ; port ISC_294
ISC_295: C39.D15M(Shutter_B) ; port ISC_295
ISC_296: C39.D15M(Shutter_C) ; port ISC_296
ISC_303: C36.D25M(Readback_Slot_2) ; port ISC_303
ISC_304: C36.D25F(Control_Slot_2) ; port ISC_304
ISC_305: C36.D25M(Readback_Slot_5) ; port ISC_305
ISC_306: C36.D25F(Control_Slot_5) ; port ISC_306
ISC_310: C37.D37M(Slot_8) ; port ISC_310
ISC_311: C37.D37M(Slot_9) ; port ISC_311
ISC_312: C38.D37M(Slot_7) ; port ISC_312
ISC_313: C38.D37M(Slot_8) ; port ISC_313
ISC_314: C39.D9F(Diverter_E) ; port ISC_314
ISC_315: C39.D9F(Diverter_F) ; port ISC_315
ISC_317: C39.D9F(Diverter_H) ; port ISC_317
ISC_318: C39.D25M(Slot_4) ; port ISC_318
ISC_319: C39.D37M(Blank) ; port ISC_319
ISC_320: C39.D37M(Slot_3) ; port ISC_320
ISC_323: C39.D15M(Shutter_D) ; port ISC_323
ISC_326: C39.D37M(Slot_9) ; port ISC_326
ISC_327: C39.D37M(Slot_8) ; port ISC_327
ISC_328: C39.D37M(Slot_10) ; port ISC_328
ISC_329: C39.D37M(Slot_7) ; port ISC_329
ISC_331: C39.D15F(Slot_11) ; port ISC_331
ISC_335: C36.D37M(Slot_13) ; port ISC_335
ISC_336: C36.RJ-45(1B) ; port ISC_336
ISC_338: C36.RJ-44(2B) ; port ISC_338
ISC_340: C35.RJ-45(AUX_1) C36.RJ-45(IN)
ISC_341: C36.RJ-45(OUT) C37.RJ-45(IN)
ISC_342: C37.RJ-45(OUT) C38.RJ-45(IN)
ISC_343: C38.RJ-45(OUT) C39.RJ-45(IN)
ISC_344: C39.RJ-45(OUT) C40.RJ-45(IN)
ISC_411: C40.D37M(Slot_13) ; port ISC_411
ISC_414: C40.D25M(Slot_9) ; port ISC_414
ISC_415: C40.D25M(Slot_10) ; port ISC_415
ISC_416: C40.D25M(Slot_11) ; port ISC_416
ISC_417: C40.D25M(Slot_12) ; port ISC_417
ISC_423: C40.D25M(Slot_8) ; port ISC_423
ISC_432: C40.D25M(Slot_6) ; port ISC_432
ISC_433: C40.D25M(Slot_7) ; port ISC_433
ISC_443: C40.D25M(Slot_2) ; port ISC_443
ISC_REMUL_118MHz: C40.D25M(Slot_3) ; port ISC_REMUL_118MHz
ISC_RF_42.375MHz: C40.D25M(Slot_4) ; port ISC_RF_42.375MHz
ISC_SQ_85: C36.D25F(Control_Slot_9) ; port ISC_SQ_85
ISC_SQ_86: C36.D25M(Readback_Slot_9) ; port ISC_SQ_86
ISC_SQ_87: C36.RJ-45(3B) ; port ISC_SQ_87
ISC_SQ_343: C40.D37M(Slot_5) ; port ISC_SQ_343
ISC_SQ_354: C37.D37M(Slot_4) ; port ISC_SQ_354
ISC_SQ_440: C36.D25F(Control_Slot_10) ; port ISC_SQ_440
ISC_SQ_441: C36.D25M(Readback_Slot_10) ; port ISC_SQ_441
ISC_SQ_508: C39.D9F(Diverter_G) ; port ISC_SQ_508
ISC_TEMP_CER: C39.M12F(Slot_6_A) Sensor_1.M12(1)
ISC_TEMP_MEZZ: C39.M12F(Slot_6_B) Sensor_2.M12(1)
TCS_42X: C36.D25M(Readback_Slot_6) ; port TCS_42X
TCS_42Y: C36.D25M(Readback_Slot_7) ; port TCS_42Y
TCS_43X: C36.D25F(Control_Slot_6) ; port TCS_43X
TCS_43Y: C36.D25F(Control_Slot_7) ; port TCS_43Y
TCS_DRV1: C36.D25M(Readback_Slot_8) ; port TCS_DRV1
TCS_DRV2: C36.D25F(Control_Slot_8) ; port TCS_DRV2

Not connected (* = marked no-connect by the designer): C35 Conec-3(+24VDC)*; C36 Conec-3(+24VDC)*; C37 Conec-3(+24VDC)*; C38 Conec-3(+24VDC)*; C39 Conec-3(+24VDC)*; C40 Conec-3(+24VDC)*

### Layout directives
Length: 144ft: ISC_2, ISC_5, ISC_6, ISC_7, ISC_27, ISC_28, ISC_47, ISC_48, ISC_68, ISC_92, ISC_93, ISC_94, ISC_121, ISC_122, ISC_178, ISC_179, ISC_180, ISC_181, ISC_182, ISC_183, ISC_199, ISC_200, ISC_201, ISC_202, ISC_204, ISC_205, ISC_206, ISC_207, ISC_210, ISC_294, ISC_295, ISC_296, ISC_303, ISC_304, ISC_305, ISC_306, ISC_310, ISC_311, ISC_312, ISC_313, ISC_314, ISC_315, ISC_317, ISC_318, ISC_319, ISC_320, ISC_323, ISC_326, ISC_327, ISC_328, ISC_329, ISC_331, ISC_414, ISC_415, ISC_416, ISC_417, ISC_423, ISC_432, ISC_433, ISC_SQ_354, TCS_42X, TCS_42Y, TCS_43X, TCS_43Y, TCS_DRV1, TCS_DRV2
Length: 6ft: ISC_340, ISC_341, ISC_342, ISC_343, ISC_344
Length: 167ft: ISC_SQ_85, ISC_SQ_86
Length: 15ft: ISC_411, ISC_REMUL_118MHz, ISC_RF_42.375MHz, ISC_SQ_343
Length: 20ft: ISC_TEMP_CER
Length: 50ft: ISC_TEMP_MEZZ
Length: 120ft: ISC_SQ_508
Length: X": Beckhoff_1
Length: 112ft: ISC_SQ_440, ISC_SQ_441
Length: 138ft: ISC_443
Length: 10ft: ISC_335

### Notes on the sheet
- ISC-C2 Rack
- No Cable
- (near T1) To Network Rack
- Next To PSL and PEM Racks
- (near C35) No Cable
- Delay_MC_A
- Delay_MC_B
- VCO_MC
- CM_A/1
- CM_A/2
- CM_B/1
- CM_B/2
- PICO HAM1/3 Controls
- PICO HAM1/3 Readback
- PICO HAM2 Controls
- PICO HAM2 Readback
- PICO HAM6 Controls
- PICO HAM6 Readback
- PICO ISCT1 Controls
- PICO ISCT1 Readback
- PICO OL Controls
- PICO OL Readback
- PICO TCSX Controls
- PICO TCSX Readback
- PICO TCSY Controls
- PICO TCSY Readback
- PICO HWS Controls
- PICO HWS Readback
- PICO SQZT0 Controls
- PICO SQZT0 Readback
- PICO HAM7 Controls
- PICO HAM7 Readback
- Serial Concentrator
- Demod A - MC/ALS
- Demod B - CM
- Demod C - POP/REFL
- Demod D - SQZ
- VCO ALS COMM
- Delay B
- RF AMP A
- RF AMP B
- Demod E - WFS MC
- Demod F - WFS RELF A
- Demod N - BHD WFS
- Demod O - BHD LSC
- Demod G - WFS REFL B
- Demod H - WFS REFL C
- Demod J - WFS AS A
- Demod K - WFS AS B
- Demod I - WFS JAC
- Demod L - WFS AS C
- Demod M - WFS SQZ
- CM SUM A
- CM SUM B
- ALS Fiber Dist.
- VCO ALS DIFF
- DCPD ISCT6
- Auxiliary ISCT6
- DCPD ISCT1
- Auxiliary ISCT1
- SHG Oven
- 3.125 MHz SQZ Pickoff
- DCPD Relays
- RF AMP D
- EOM Driver A PSL
- EOM Driver B PSL
- Fast Shutter 1 HAM6
- RF AMP C
- PLL ALS COMM
- FDD ALS COMM
- PLL ALS DIFF
- FDD ALS DIFF

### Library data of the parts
C35 = Corner 1 EtherCat: Serial: Sxxxxxxx; System: ISC
C36 = Corner 2 EtherCat: Serial: Sxxxxxxx; System: ISC
C37 = Corner 3 EtherCat: Serial: Sxxxxxxx; System: ISC
C38 = Corner 4 EtherCat: Serial: Sxxxxxxx; System: ISC
C39 = Corner 5 EtherCat: Serial: Sxxxxxxx; System: ISC
C40 = Corner 6 EtherCat: Serial: Sxxxxxxx; System: ISC
Sensor_1 Sensor_2 = Placeholder: Placeholder Location; Serial: Sxxxxxxx; System: ISC; DCC: tbd
T1 = Placeholder: Serial: Sxxxxxxx; System: ISC; DCC: tbd

## Sheet ISC_C3_SH1.SchDoc: ISC System Wiring Diagram
size B; DrawnBy: Filiberto Clara; Engineer: Filiberto Clara; Organization: LIGO Laboratory; Address1: California Institute of Technology; Address2: Massachusetts Institute of Technology; DocumentNumber: D1900511; Revision: V11; SheetNumber: 5; SheetTotal: 39
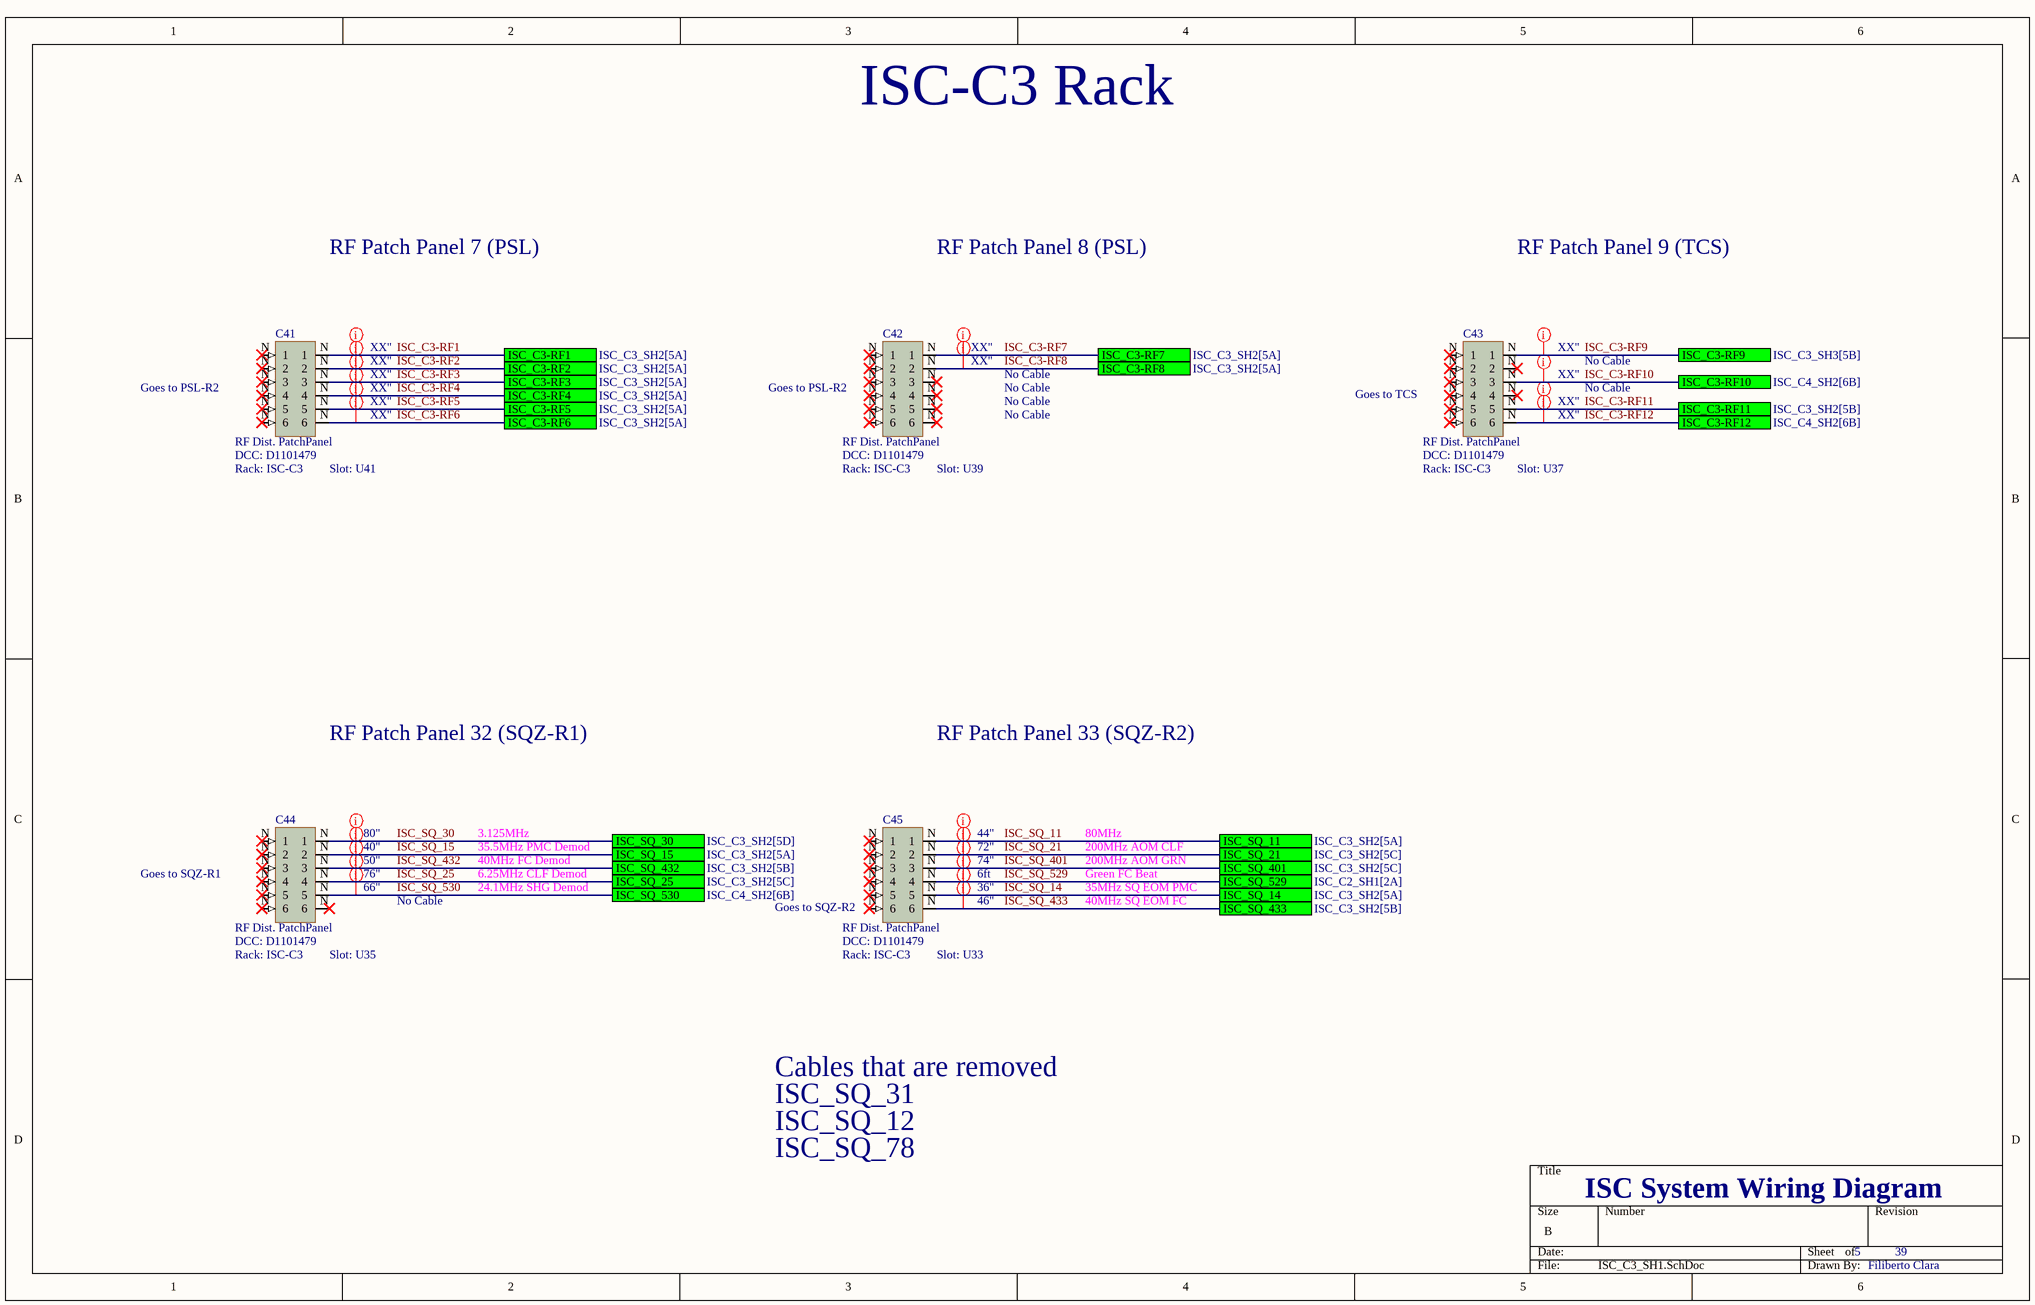
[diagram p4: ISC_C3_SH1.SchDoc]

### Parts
C41  RF Dist. PatchPanel  DCC: D1101479  Rack: ISC-C3  Slot: U41
C42  RF Dist. PatchPanel  DCC: D1101479  Rack: ISC-C3  Slot: U39
C43  RF Dist. PatchPanel  DCC: D1101479  Rack: ISC-C3  Slot: U37
C44  RF Dist. PatchPanel  DCC: D1101479  Rack: ISC-C3  Slot: U35
C45  RF Dist. PatchPanel  DCC: D1101479  Rack: ISC-C3  Slot: U33

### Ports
ISC_C3-RF1 (see ISC_C3_SH2[5A]), ISC_C3-RF2 (see ISC_C3_SH2[5A]), ISC_C3-RF3 (see ISC_C3_SH2[5A]), ISC_C3-RF4 (see ISC_C3_SH2[5A]), ISC_C3-RF5 (see ISC_C3_SH2[5A]), ISC_C3-RF6 (see ISC_C3_SH2[5A]), ISC_C3-RF7 (see ISC_C3_SH2[5A]), ISC_C3-RF8 (see ISC_C3_SH2[5A]), ISC_C3-RF9 (see ISC_C3_SH3[5B]), ISC_C3-RF10 (see ISC_C4_SH2[6B]), ISC_C3-RF11 (see ISC_C3_SH2[5B]), ISC_C3-RF12 (see ISC_C4_SH2[6B]), ISC_SQ_11 (see ISC_C3_SH2[5A]), ISC_SQ_14 (see ISC_C3_SH2[5A]), ISC_SQ_15 (see ISC_C3_SH2[5A]), ISC_SQ_21 (see ISC_C3_SH2[5C]), ISC_SQ_25 (see ISC_C3_SH2[5C]), ISC_SQ_30 (see ISC_C3_SH2[5D]), ISC_SQ_401 (see ISC_C3_SH2[5C]), ISC_SQ_432 (see ISC_C3_SH2[5B]), ISC_SQ_433 (see ISC_C3_SH2[5B]), ISC_SQ_529 (see ISC_C2_SH1[2A]), ISC_SQ_530 (see ISC_C4_SH2[6B])

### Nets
ISC_C3-RF1: C41.N(1) ; port ISC_C3-RF1
ISC_C3-RF2: C41.N(2) ; port ISC_C3-RF2
ISC_C3-RF3: C41.N(3) ; port ISC_C3-RF3
ISC_C3-RF4: C41.N(4) ; port ISC_C3-RF4
ISC_C3-RF5: C41.N(5) ; port ISC_C3-RF5
ISC_C3-RF6: C41.N(6) ; port ISC_C3-RF6
ISC_C3-RF7: C42.N(1) ; port ISC_C3-RF7
ISC_C3-RF8: C42.N(2) ; port ISC_C3-RF8
ISC_C3-RF9: C43.N(1) ; port ISC_C3-RF9
ISC_C3-RF10: C43.N(3) ; port ISC_C3-RF10
ISC_C3-RF11: C43.N(5) ; port ISC_C3-RF11
ISC_C3-RF12: C43.N(6) ; port ISC_C3-RF12
ISC_SQ_11: C45.N(1) ; port ISC_SQ_11
ISC_SQ_14: C45.N(5) ; port ISC_SQ_14
ISC_SQ_15: C44.N(2) ; port ISC_SQ_15
ISC_SQ_21: C45.N(2) ; port ISC_SQ_21
ISC_SQ_25: C44.N(4) ; port ISC_SQ_25
ISC_SQ_30: C44.N(1) ; port ISC_SQ_30
ISC_SQ_401: C45.N(3) ; port ISC_SQ_401
ISC_SQ_432: C44.N(3) ; port ISC_SQ_432
ISC_SQ_433: C45.N(6) ; port ISC_SQ_433
ISC_SQ_529: C45.N(4) ; port ISC_SQ_529
ISC_SQ_530: C44.N(5) ; port ISC_SQ_530

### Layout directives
Length: XX": ISC_C3-RF1, ISC_C3-RF2, ISC_C3-RF3, ISC_C3-RF4, ISC_C3-RF5, ISC_C3-RF6, ISC_C3-RF7, ISC_C3-RF8, ISC_C3-RF9, ISC_C3-RF10, ISC_C3-RF11, ISC_C3-RF12
Length: 36": ISC_SQ_14
Length: 44": ISC_SQ_11
Length: 80": ISC_SQ_30
Length: 66": ISC_SQ_530
Length: 50": ISC_SQ_432
Length: 76": ISC_SQ_25
Length: 72": ISC_SQ_21
Length: 74": ISC_SQ_401
Length: 46": ISC_SQ_433
Length: 6ft: ISC_SQ_529
Length: 40": ISC_SQ_15

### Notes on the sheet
- ISC-C3 Rack
- RF Patch Panel 7 (PSL)
- RF Patch Panel 8 (PSL)
- RF Patch Panel 9 (TCS)
- No Cable
- (near C41) Goes to PSL-R2
- (near C42) Goes to PSL-R2
- (near C43) Goes to TCS
- RF Patch Panel 32 (SQZ-R1)
- RF Patch Panel 33 (SQZ-R2)
- 3.125MHz
- 35.5MHz PMC Demod
- 80MHz
- 200MHz AOM CLF
- (near C44) Goes to SQZ-R1
- 24.1MHz SHG Demod
- 40MHz FC Demod
- 6.25MHz CLF Demod
- (near C45) Goes to SQZ-R2
- 200MHz AOM GRN
- 35MHz SQ EOM PMC
- 40MHz SQ EOM FC
- Green FC Beat
- Cables that are removed
- ISC_SQ_31
- ISC_SQ_12
- ISC_SQ_78

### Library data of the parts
C41-C45 = RF Dist. PatchPanel: Serial: Sxxxxxxx; System: ISC

## Sheet ISC_C3_SH2.SchDoc: ISC System Wiring Diagram
size C; DrawnBy: Filiberto Clara; Engineer: Filiberto Clara; Organization: LIGO Laboratory; Address1: California Institute of Technology; Address2: Massachusetts Institute of Technology; DocumentNumber: D1900511; Revision: V11; SheetNumber: 6; SheetTotal: 39
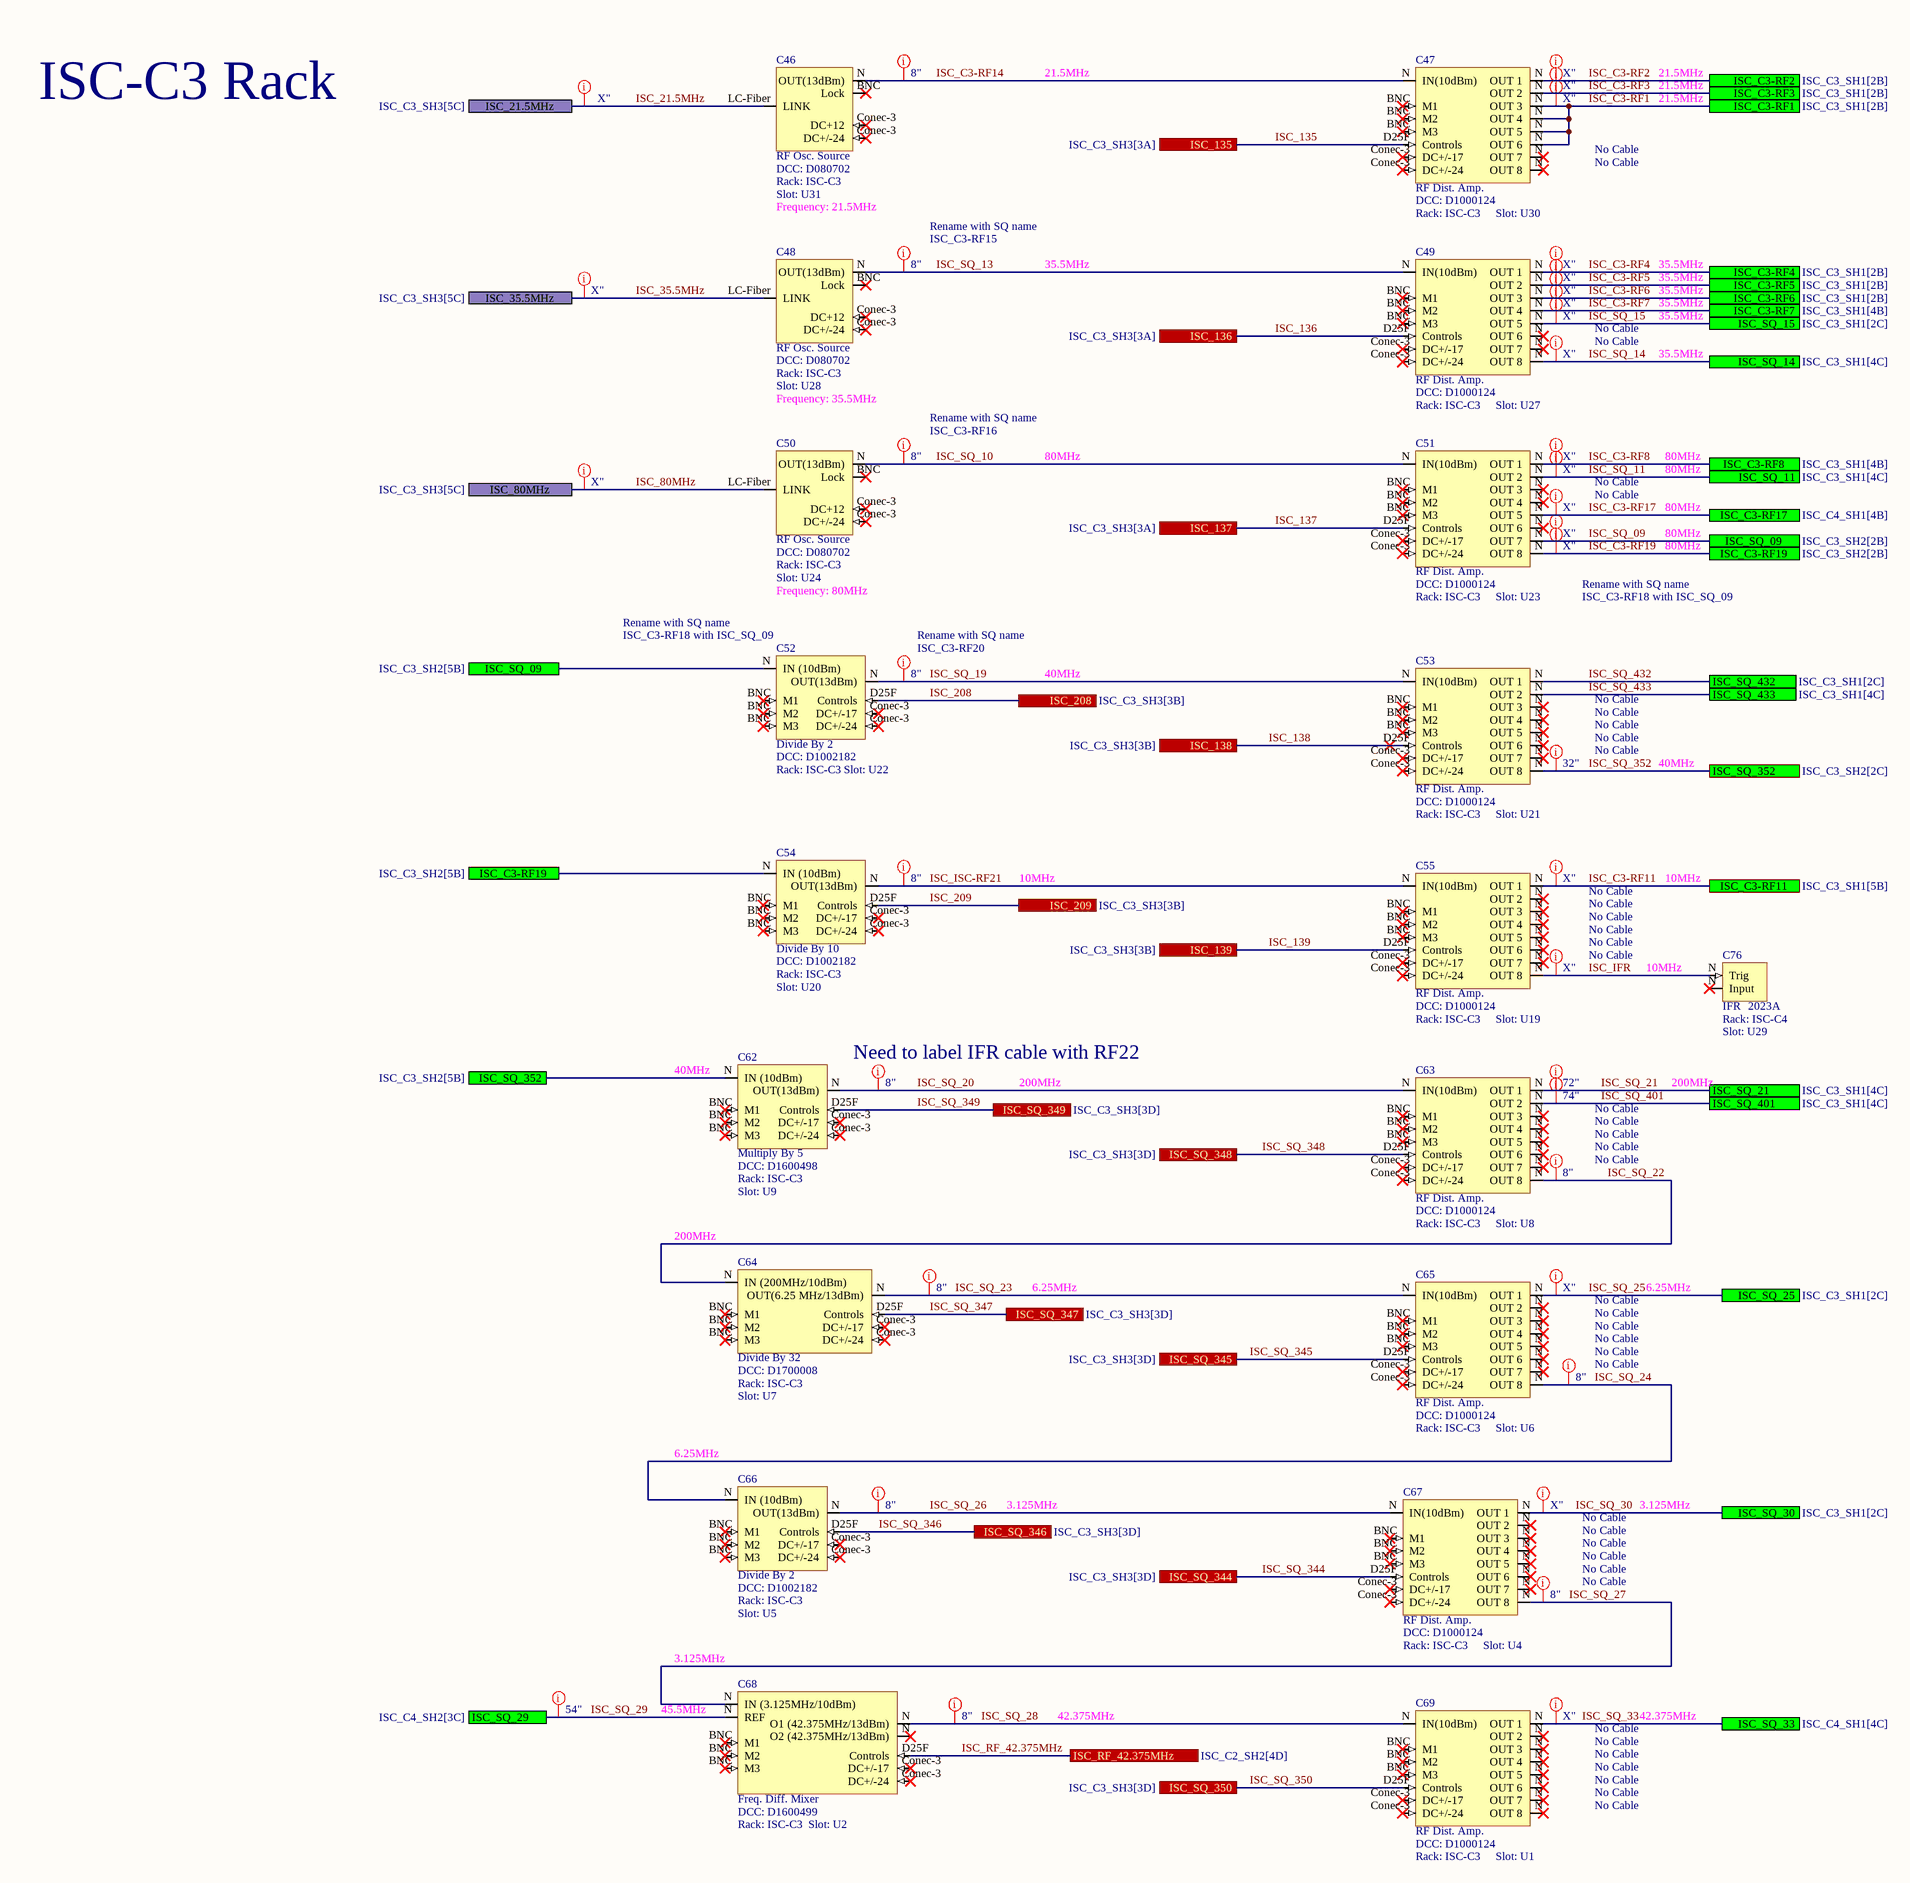
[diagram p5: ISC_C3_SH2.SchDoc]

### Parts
C46  RF Osc. Source  DCC: D080702  Rack: ISC-C3  Slot: U31  Frequency: 21.5MHz
C47  RF Dist. Amp.  DCC: D1000124  Rack: ISC-C3  Slot: U30
C48  RF Osc. Source  DCC: D080702  Rack: ISC-C3  Slot: U28  Frequency: 35.5MHz
C49  RF Dist. Amp.  DCC: D1000124  Rack: ISC-C3  Slot: U27
C50  RF Osc. Source  DCC: D080702  Rack: ISC-C3  Slot: U24  Frequency: 80MHz
C51  RF Dist. Amp.  DCC: D1000124  Rack: ISC-C3  Slot: U23
C52  Divide By 2  DCC: D1002182  Rack: ISC-C3  Slot: U22
C53  RF Dist. Amp.  DCC: D1000124  Rack: ISC-C3  Slot: U21
C54  Divide By 10  DCC: D1002182  Rack: ISC-C3  Slot: U20
C55  RF Dist. Amp.  DCC: D1000124  Rack: ISC-C3  Slot: U19
C62  Multiply By 5  DCC: D1600498  Rack: ISC-C3  Slot: U9
C63  RF Dist. Amp.  DCC: D1000124  Rack: ISC-C3  Slot: U8
C64  Divide By 32  DCC: D1700008  Rack: ISC-C3  Slot: U7
C65  RF Dist. Amp.  DCC: D1000124  Rack: ISC-C3  Slot: U6
C66  Divide By 2  DCC: D1002182  Rack: ISC-C3  Slot: U5
C67  RF Dist. Amp.  DCC: D1000124  Rack: ISC-C3  Slot: U4
C68  Freq. Diff. Mixer  DCC: D1600499  Rack: ISC-C3  Slot: U2
C69  RF Dist. Amp.  DCC: D1000124  Rack: ISC-C3  Slot: U1
C76  2023A  Rack: ISC-C4  Slot: U29

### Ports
ISC_21.5MHz (see ISC_C3_SH3[5C]), ISC_35.5MHz (see ISC_C3_SH3[5C]), ISC_80MHz (see ISC_C3_SH3[5C]), ISC_135 (see ISC_C3_SH3[3A]), ISC_136 (see ISC_C3_SH3[3A]), ISC_137 (see ISC_C3_SH3[3A]), ISC_138 (see ISC_C3_SH3[3B]), ISC_139 (see ISC_C3_SH3[3B]), ISC_208 (see ISC_C3_SH3[3B]), ISC_209 (see ISC_C3_SH3[3B]), ISC_C3-RF1 (see ISC_C3_SH1[2B]), ISC_C3-RF2 (see ISC_C3_SH1[2B]), ISC_C3-RF3 (see ISC_C3_SH1[2B]), ISC_C3-RF4 (see ISC_C3_SH1[2B]), ISC_C3-RF5 (see ISC_C3_SH1[2B]), ISC_C3-RF6 (see ISC_C3_SH1[2B]), ISC_C3-RF7 (see ISC_C3_SH1[4B]), ISC_C3-RF8 (see ISC_C3_SH1[4B]), ISC_C3-RF11 (see ISC_C3_SH1[5B]), ISC_C3-RF17 (see ISC_C4_SH1[4B]), ISC_C3-RF19 (see ISC_C3_SH2[2B]), ISC_C3-RF19 (see ISC_C3_SH2[5B]), ISC_RF_42.375MHz (see ISC_C2_SH2[4D]), ISC_SQ_09 (see ISC_C3_SH2[2B]), ISC_SQ_09 (see ISC_C3_SH2[5B]), ISC_SQ_11 (see ISC_C3_SH1[4C]), ISC_SQ_14 (see ISC_C3_SH1[4C]), ISC_SQ_15 (see ISC_C3_SH1[2C]), ISC_SQ_21 (see ISC_C3_SH1[4C]), ISC_SQ_25 (see ISC_C3_SH1[2C]), ISC_SQ_29 (see ISC_C4_SH2[3C]), ISC_SQ_30 (see ISC_C3_SH1[2C]), ISC_SQ_33 (see ISC_C4_SH1[4C]), ISC_SQ_344 (see ISC_C3_SH3[3D]), ISC_SQ_345 (see ISC_C3_SH3[3D]), ISC_SQ_346 (see ISC_C3_SH3[3D]), ISC_SQ_347 (see ISC_C3_SH3[3D]), ISC_SQ_348 (see ISC_C3_SH3[3D]), ISC_SQ_349 (see ISC_C3_SH3[3D]), ISC_SQ_350 (see ISC_C3_SH3[3D]), ISC_SQ_352 (see ISC_C3_SH2[2C]), ISC_SQ_352 (see ISC_C3_SH2[5B]), ISC_SQ_401 (see ISC_C3_SH1[4C]), ISC_SQ_432 (see ISC_C3_SH1[2C]), ISC_SQ_433 (see ISC_C3_SH1[4C])

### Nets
ISC_21.5MHz: C46.LC-Fiber(LINK) ; port ISC_21.5MHz
ISC_35.5MHz: C48.LC-Fiber(LINK) ; port ISC_35.5MHz
ISC_80MHz: C50.LC-Fiber(LINK) ; port ISC_80MHz
ISC_135: C47.D25F(Controls) ; port ISC_135
ISC_136: C49.D25F(Controls) ; port ISC_136
ISC_137: C51.D25F(Controls) ; port ISC_137
ISC_138: C53.D25F(Controls) ; port ISC_138
ISC_139: C55.D25F(Controls) ; port ISC_139
ISC_208: C52.D25F(Controls) ; port ISC_208
ISC_209: C54.D25F(Controls) ; port ISC_209
ISC_C3-RF1: C47.N(OUT_3) ; port ISC_C3-RF1
ISC_C3-RF2: C47.N(OUT_1) ; port ISC_C3-RF2
ISC_C3-RF3: C47.N(OUT_2) ; port ISC_C3-RF3
ISC_C3-RF4: C49.N(OUT_1) ; port ISC_C3-RF4
ISC_C3-RF5: C49.N(OUT_2) ; port ISC_C3-RF5
ISC_C3-RF6: C49.N(OUT_3) ; port ISC_C3-RF6
ISC_C3-RF7: C49.N(OUT_4) ; port ISC_C3-RF7
ISC_C3-RF8: C51.N(OUT_1) ; port ISC_C3-RF8
ISC_C3-RF11: C55.N(OUT_1) ; port ISC_C3-RF11
ISC_C3-RF14: C46.N(OUT(13dBm)) C47.N(IN(10dBm))
ISC_C3-RF17: C51.N(OUT_5) ; port ISC_C3-RF17
ISC_C3-RF19: C51.N(OUT_8) C54.N(IN_(10dBm)) ; port ISC_C3-RF19
ISC_IFR: C55.N(OUT_8) C76.N(Input)
ISC_ISC-RF21: C54.N(OUT(13dBm)) C55.N(IN(10dBm))
ISC_RF_42.375MHz: C68.D25F(Controls) ; port ISC_RF_42.375MHz
ISC_SQ_09: C51.N(OUT_7) C52.N(IN_(10dBm)) ; port ISC_SQ_09
ISC_SQ_10: C50.N(OUT(13dBm)) C51.N(IN(10dBm))
ISC_SQ_11: C51.N(OUT_2) ; port ISC_SQ_11
ISC_SQ_13: C48.N(OUT(13dBm)) C49.N(IN(10dBm))
ISC_SQ_14: C49.N(OUT_8) ; port ISC_SQ_14
ISC_SQ_15: C49.N(OUT_5) ; port ISC_SQ_15
ISC_SQ_19: C52.N(OUT(13dBm)) C53.N(IN(10dBm))
ISC_SQ_20: C62.N(OUT(13dBm)) C63.N(IN(10dBm))
ISC_SQ_21: C63.N(OUT_1) ; port ISC_SQ_21
ISC_SQ_22: C63.N(OUT_8) C64.N(IN_(200MHz/10dBm))
ISC_SQ_23: C64.N(OUT(6.25_MHz/13dBm)) C65.N(IN(10dBm))
ISC_SQ_24: C65.N(OUT_8) C66.N(IN_(10dBm))
ISC_SQ_25: C65.N(OUT_1) ; port ISC_SQ_25
ISC_SQ_26: C66.N(OUT(13dBm)) C67.N(IN(10dBm))
ISC_SQ_27: C67.N(OUT_8) C68.N(IN_(3.125MHz/10dBm))
ISC_SQ_28: C68.N(O1_(42.375MHz/13dBm)) C69.N(IN(10dBm))
ISC_SQ_29: C68.N(REF) ; port ISC_SQ_29
ISC_SQ_30: C67.N(OUT_1) ; port ISC_SQ_30
ISC_SQ_33: C69.N(OUT_1) ; port ISC_SQ_33
ISC_SQ_344: C67.D25F(Controls) ; port ISC_SQ_344
ISC_SQ_345: C65.D25F(Controls) ; port ISC_SQ_345
ISC_SQ_346: C66.D25F(Controls) ; port ISC_SQ_346
ISC_SQ_347: C64.D25F(Controls) ; port ISC_SQ_347
ISC_SQ_348: C63.D25F(Controls) ; port ISC_SQ_348
ISC_SQ_349: C62.D25F(Controls) ; port ISC_SQ_349
ISC_SQ_350: C69.D25F(Controls) ; port ISC_SQ_350
ISC_SQ_352: C53.N(OUT_8) C62.N(IN_(10dBm)) ; port ISC_SQ_352
ISC_SQ_401: C63.N(OUT_2) ; port ISC_SQ_401
ISC_SQ_432: C53.N(OUT_1) ; port ISC_SQ_432
ISC_SQ_433: C53.N(OUT_2) ; port ISC_SQ_433

Not connected (* = marked no-connect by the designer): C46 BNC(Lock)* Conec-3(DC+12)*; C47 BNC(M1)* Conec-3(DC+/-17)*; C48 BNC(Lock)* Conec-3(DC+12)*; C49 BNC(M1)* Conec-3(DC+/-17)*; C50 BNC(Lock)* Conec-3(DC+12)*; C51 BNC(M1)* Conec-3(DC+/-17)*; C52 BNC(M1)* Conec-3(DC+/-17)*; C53 BNC(M1)* Conec-3(DC+/-17)*; C54 BNC(M1)* Conec-3(DC+/-17)*; C55 BNC(M1)* Conec-3(DC+/-17)*; C62 BNC(M1)* Conec-3(DC+/-17)*; C63 BNC(M1)* Conec-3(DC+/-17)*; C64 BNC(M1)* Conec-3(DC+/-17)*; C65 BNC(M1)* Conec-3(DC+/-17)*; C66 BNC(M1)* Conec-3(DC+/-17)*; C67 BNC(M1)* Conec-3(DC+/-17)*; C68 BNC(M1)* Conec-3(DC+/-17)*; C69 BNC(M1)* Conec-3(DC+/-17)*

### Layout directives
Length: 8": ISC_C3-RF14, ISC_ISC-RF21, ISC_SQ_10, ISC_SQ_13, ISC_SQ_19, ISC_SQ_20, ISC_SQ_22, ISC_SQ_23, ISC_SQ_24, ISC_SQ_26, ISC_SQ_27, ISC_SQ_28
Length: 32": ISC_SQ_352
Length: 72": ISC_SQ_21
Length: X": ISC_21.5MHz, ISC_35.5MHz, ISC_80MHz, ISC_C3-RF1, ISC_C3-RF2, ISC_C3-RF3, ISC_C3-RF4, ISC_C3-RF5, ISC_C3-RF6, ISC_C3-RF7, ISC_C3-RF8, ISC_C3-RF11, ISC_C3-RF17, ISC_C3-RF19, ISC_IFR, ISC_SQ_09, ISC_SQ_11, ISC_SQ_14, ISC_SQ_15, ISC_SQ_25, ISC_SQ_30, ISC_SQ_33
Length: 54": ISC_SQ_29
Length: 74": ISC_SQ_401

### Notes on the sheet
- ISC-C3 Rack
- 21.5MHz
- No Cable
- ISC_C3-RF15
- Rename with SQ name
- 35.5MHz
- ISC_C3-RF16
- 80MHz
- ISC_C3-RF18 with ISC_SQ_09
- (near C52) ISC_C3-RF18 with ISC_SQ_09
- ISC_C3-RF20
- 40MHz
- 10MHz
- (near C76) 10MHz
- (near C62) 40MHz
- (near C62) Need to label IFR cable with RF22
- 200MHz
- (near C64) 200MHz
- 6.25MHz
- (near C66) 6.25MHz
- 3.125MHz
- (near C68) 3.125MHz
- (near C68) 45.5MHz
- 42.375MHz

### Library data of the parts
C46 C48 C50 = RF Osc. Source: Serial: Sxxxxxxx; System: ISC
C47 C49 C51 = RF Distribution Amplifier: Serial: Sxxxxxxx; System: ISC
C52 = Divide By 2: Serial: Sxxxxxxx; System: ISC; Frequency: 40MHz
C53 C55 C63 C65 C67 = RF Distribution Amplifier: Serial: Sxxxxxxx; System: ISC; Frequency: 6.25MHz
C54 = Divide By 10: Serial: Sxxxxxxx; System: ISC; Frequency: 3.125MHz
C62 = Divide By 2: Divide By 5; Serial: Sxxxxxxx; System: ISC; Frequency: 3.125MHz
C64 = Divide By 32: Serial: Sxxxxxxx; System: ISC; Frequency: 6.25MHz
C66 = Divide By 2: Serial: Sxxxxxxx; System: ISC; Frequency: 3.125MHz
C68 = Freq. Diff. Mixer: Serial: Sxxxxxxx; System: ISC; Frequency: 42.375MHz
C69 = RF Distribution Amplifier: Serial: Sxxxxxxx; System: ISC; Frequency: 42.375MHz
C76 = Aeroflex: IFR; Serial: Sxxxxxxx; System: ISC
